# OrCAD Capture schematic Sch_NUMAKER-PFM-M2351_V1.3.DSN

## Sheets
1 Page09_SPI Flash: size A4; title: SPI Flash(W77FXX); rev: V1.3; note: NuMaker-PFM-M2351
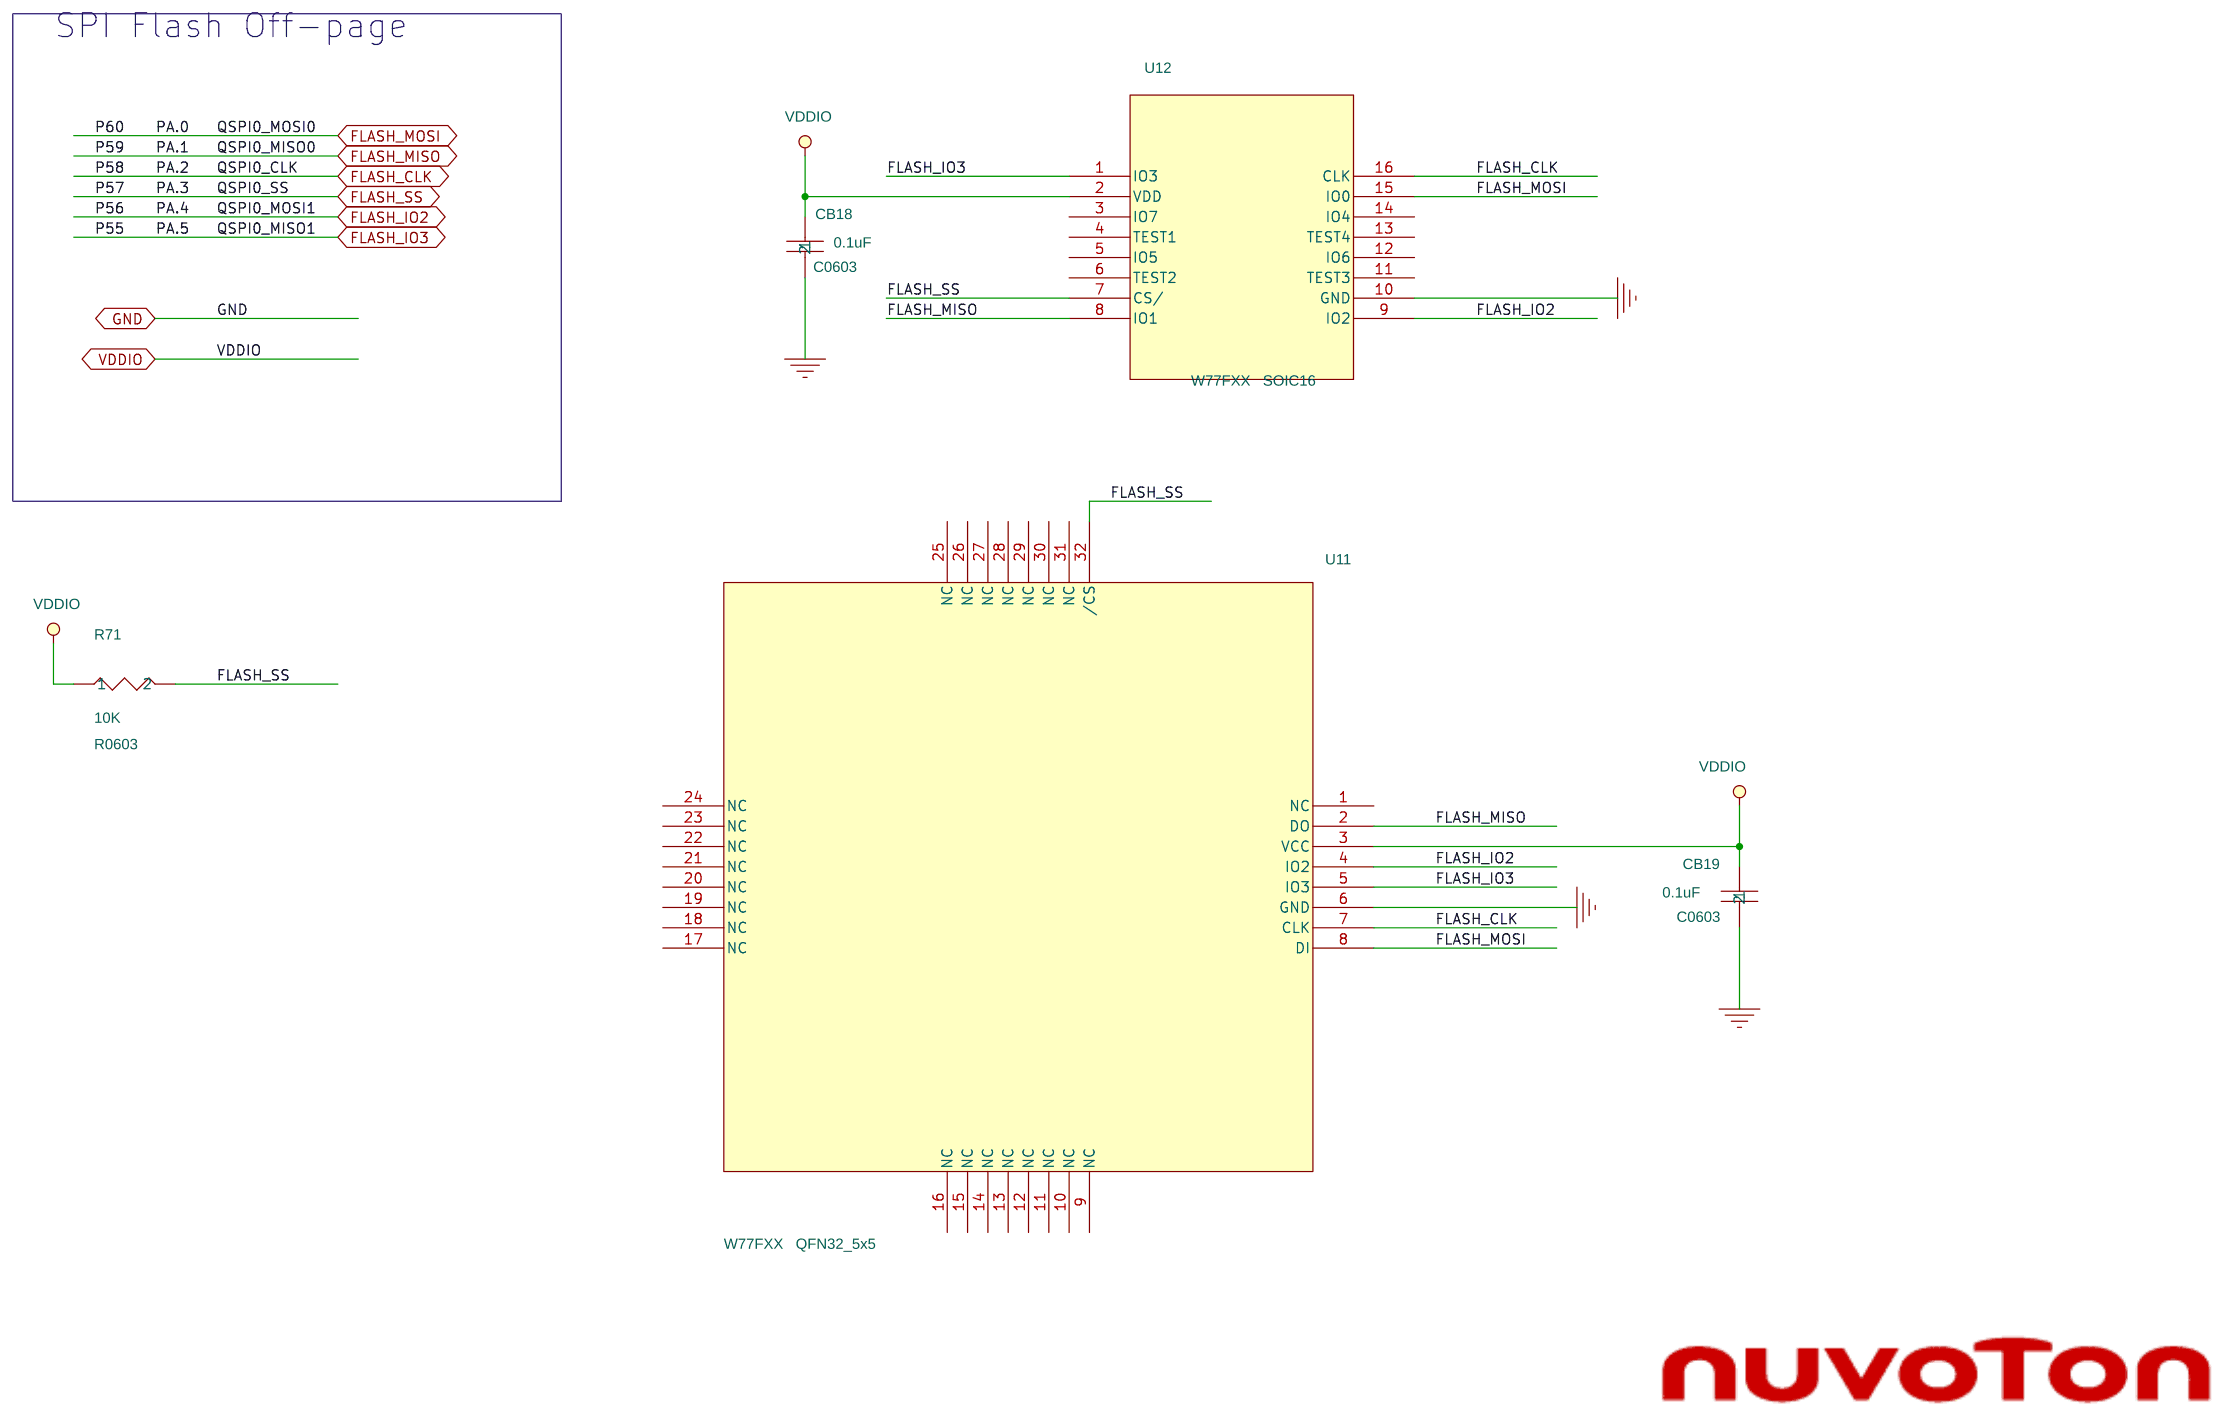
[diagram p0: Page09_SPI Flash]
2 Page08_WIFI Module: size A4; title: WIFI Module(ESP-03)
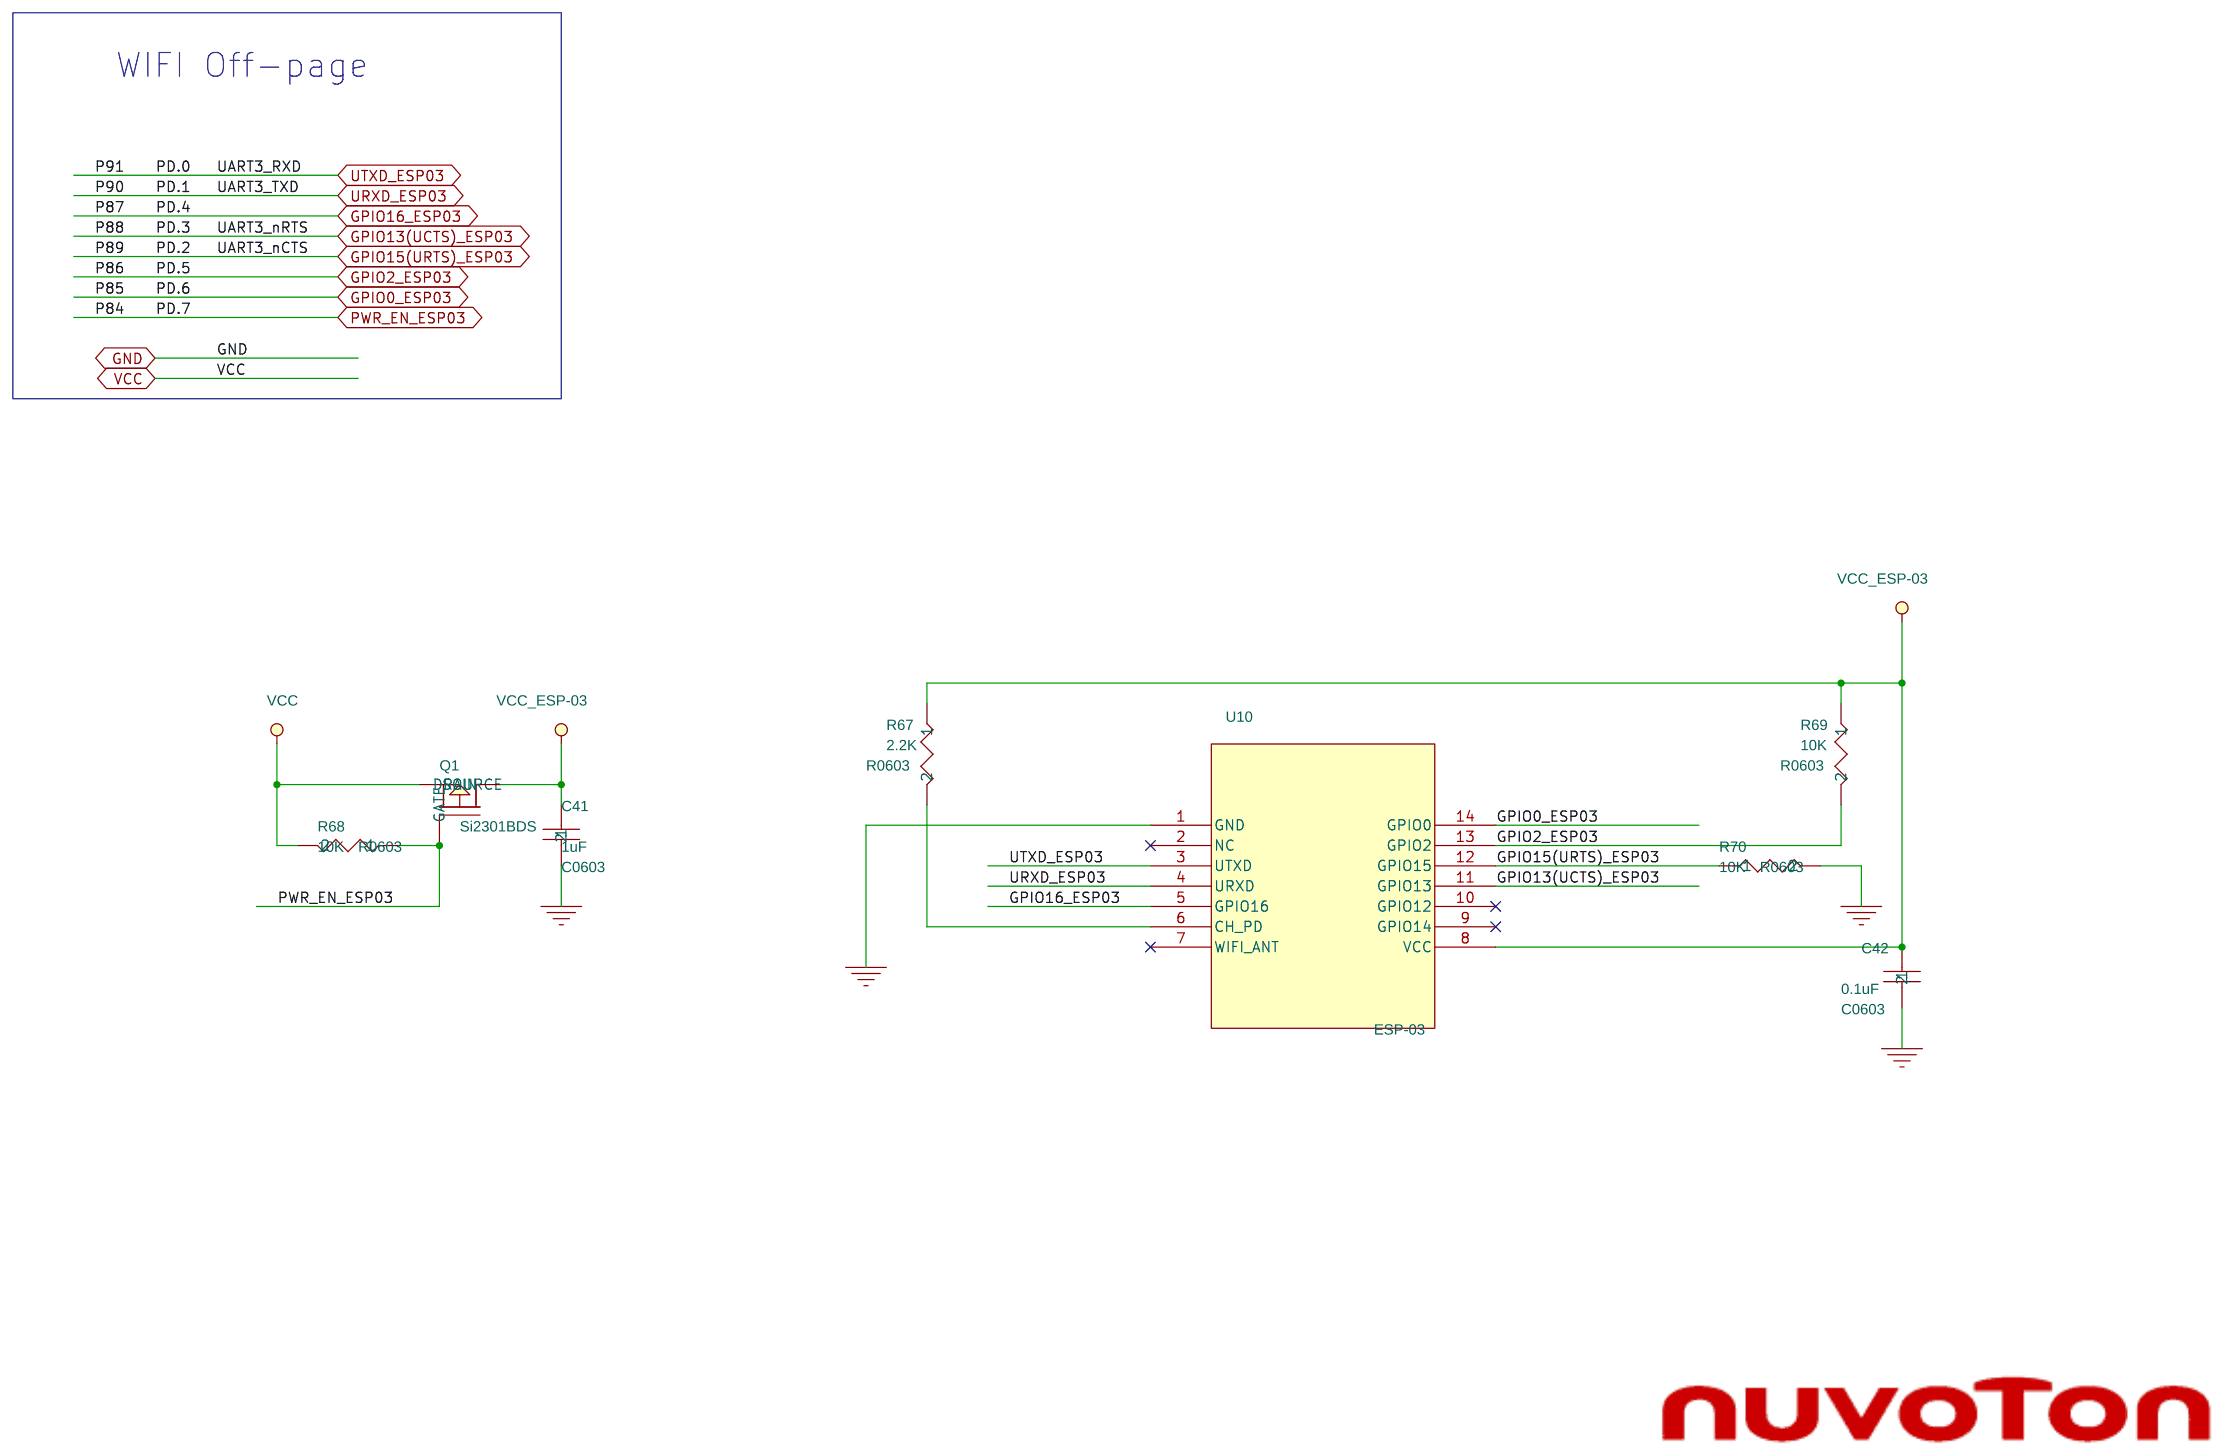
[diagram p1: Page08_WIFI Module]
3 Page00_Nu-Link-Me V3.0: size Custom; title: Nu-Link-Me(V3.0)
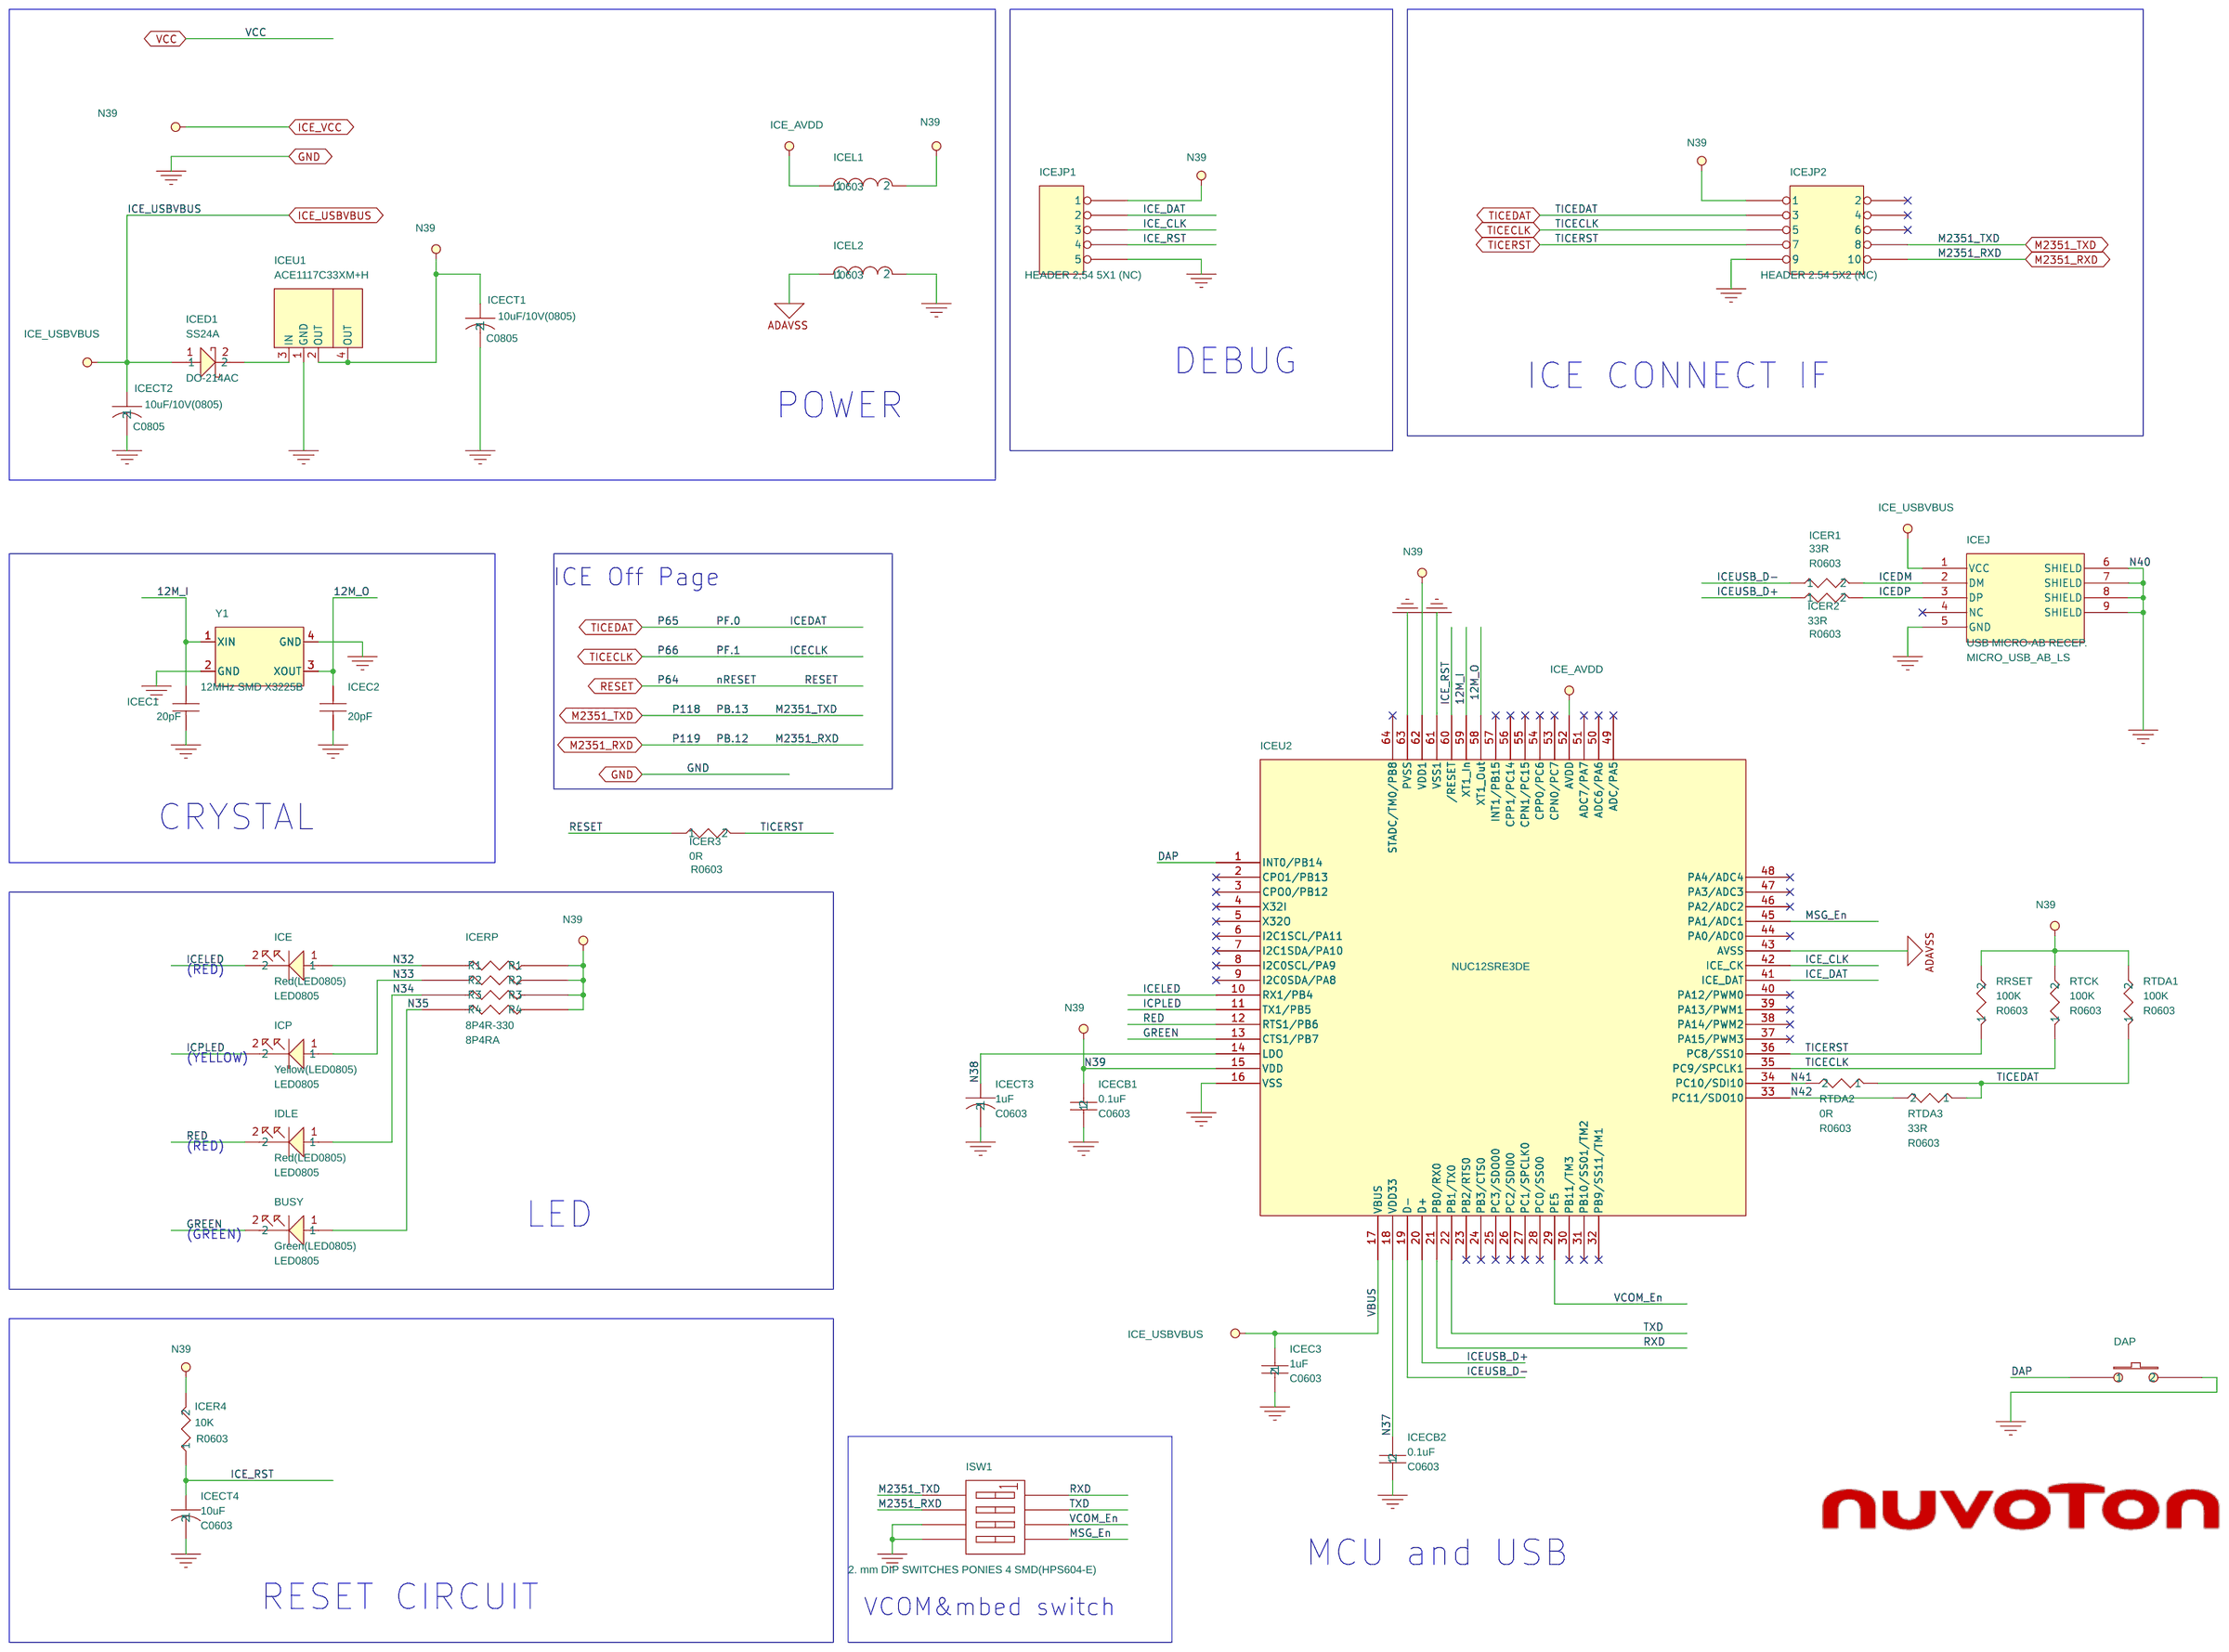
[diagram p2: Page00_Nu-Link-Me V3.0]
4 Page01_M2351 MCU: size Custom; title: M2351KIAAE(LQFP128) MCU
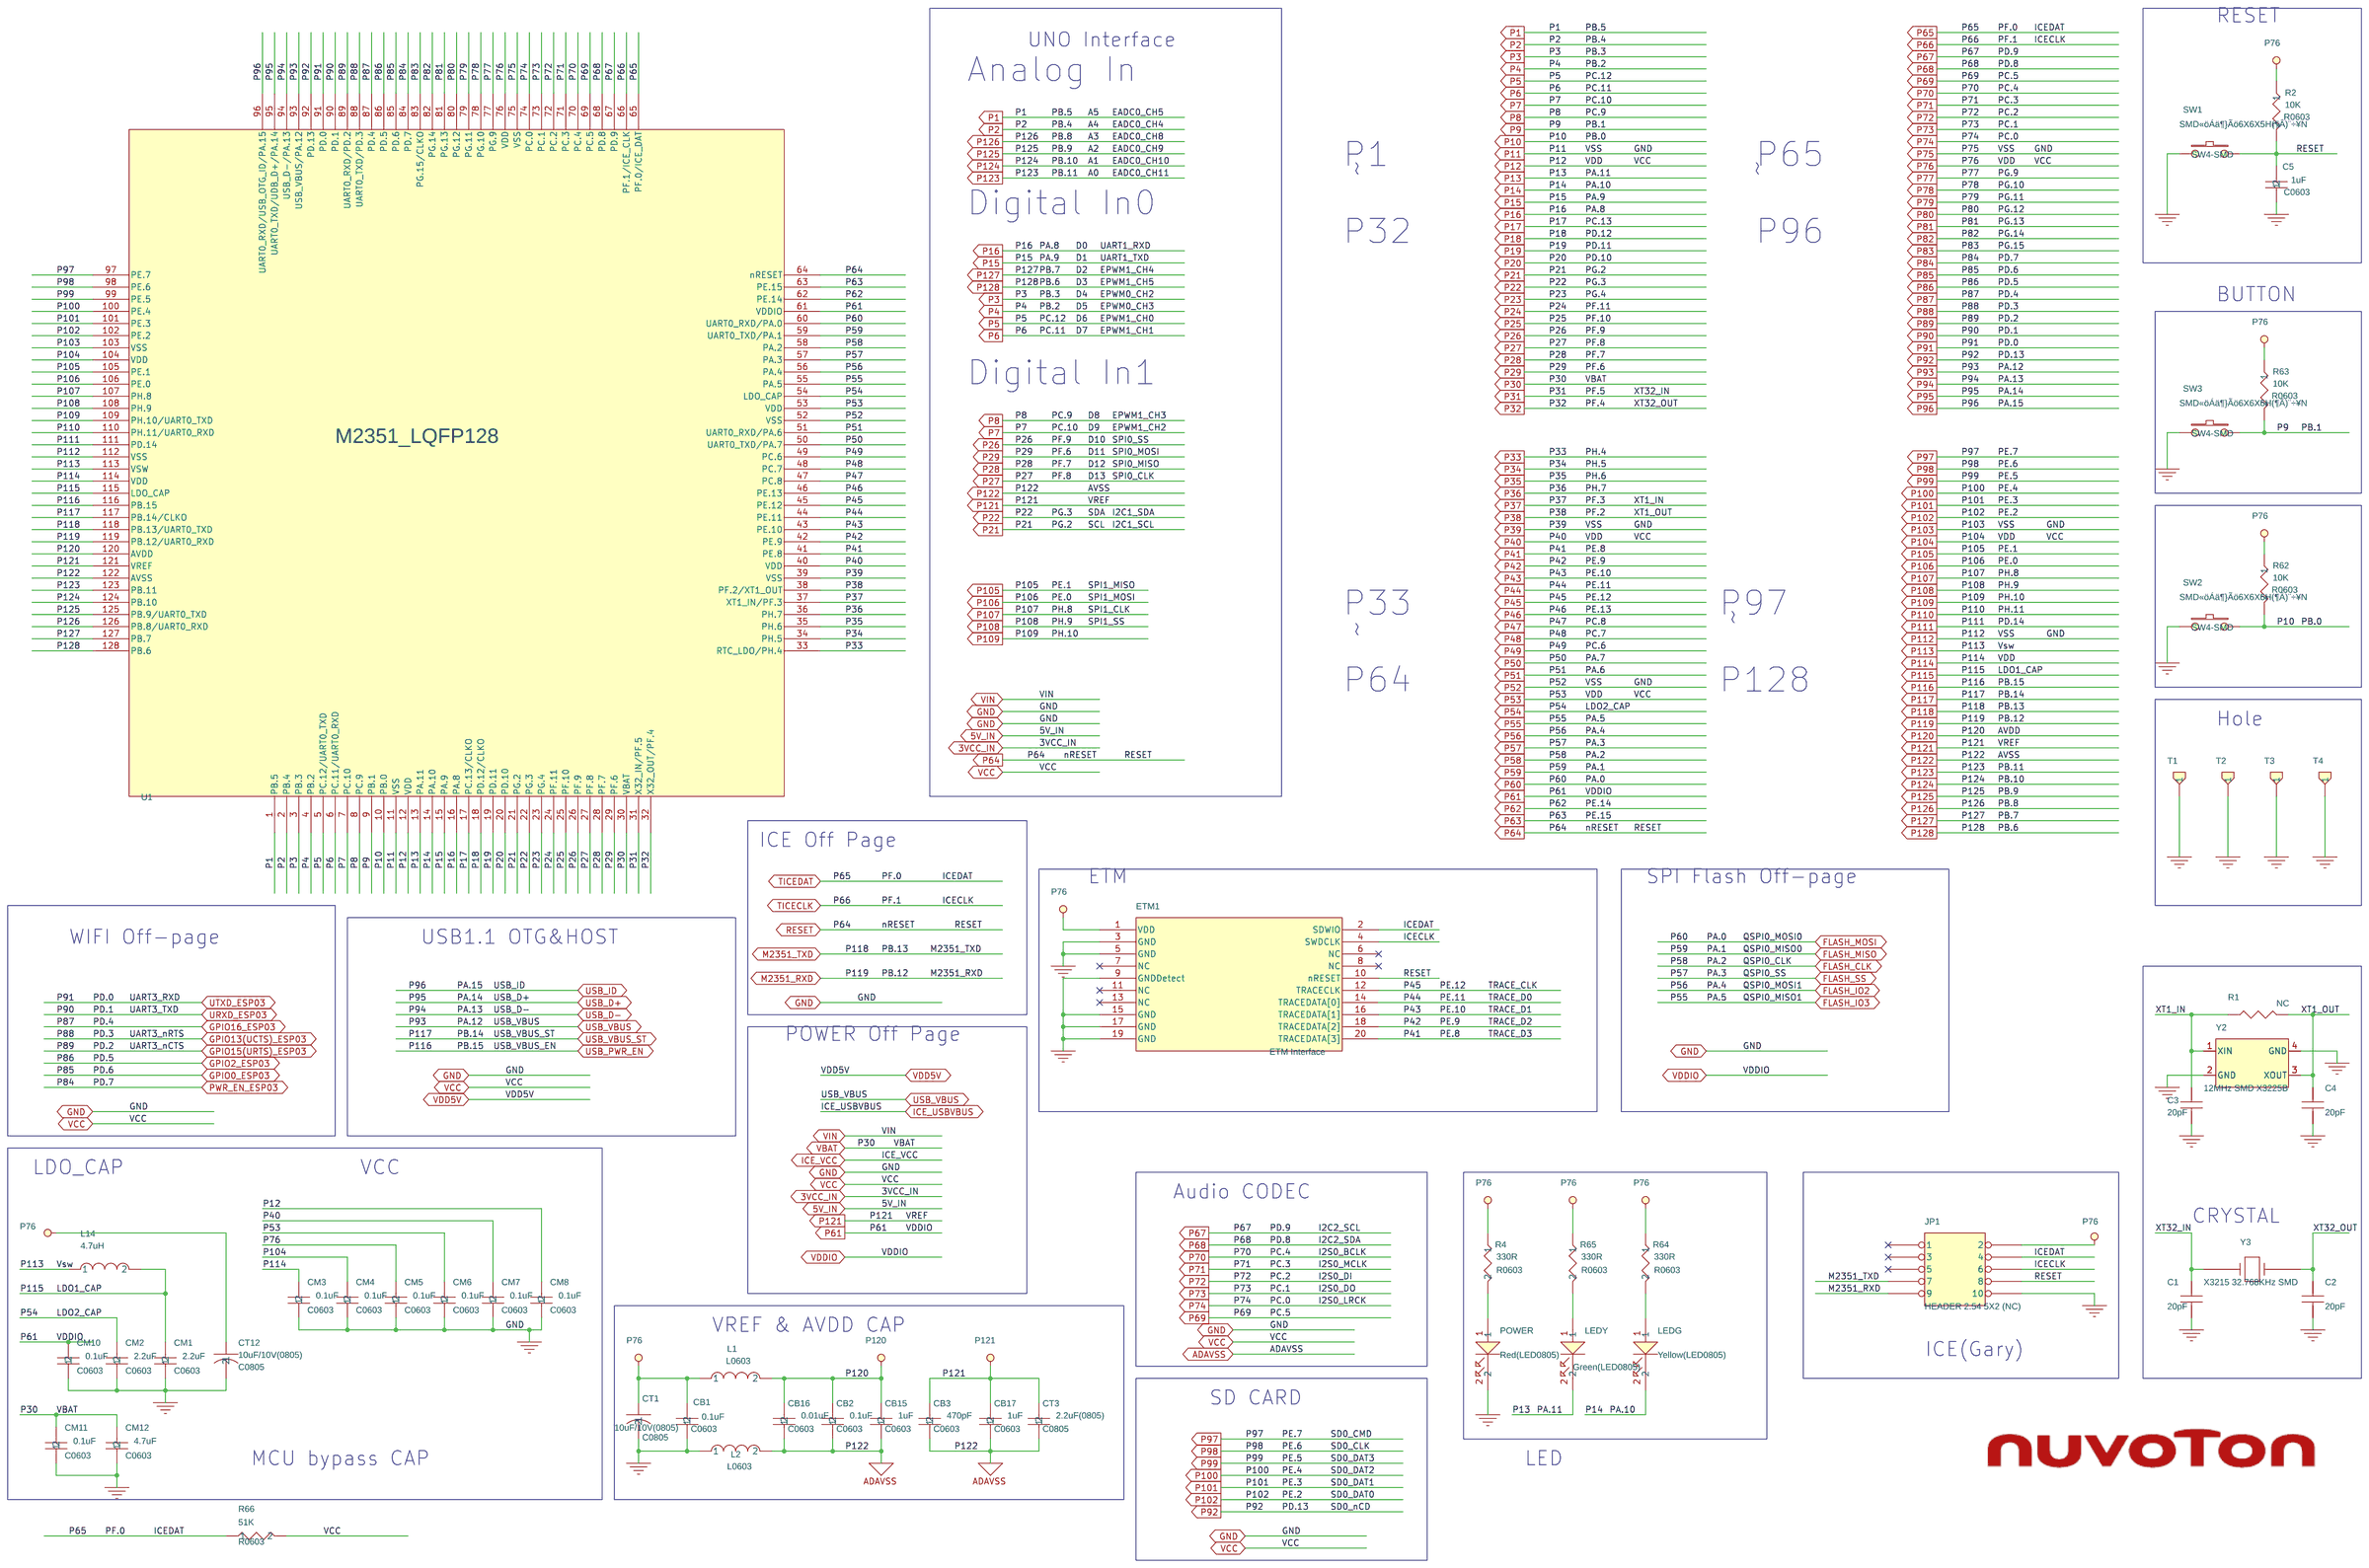
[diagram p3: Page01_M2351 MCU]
5 Page02_USB OTG Host Device: size A4; title: USB OTG
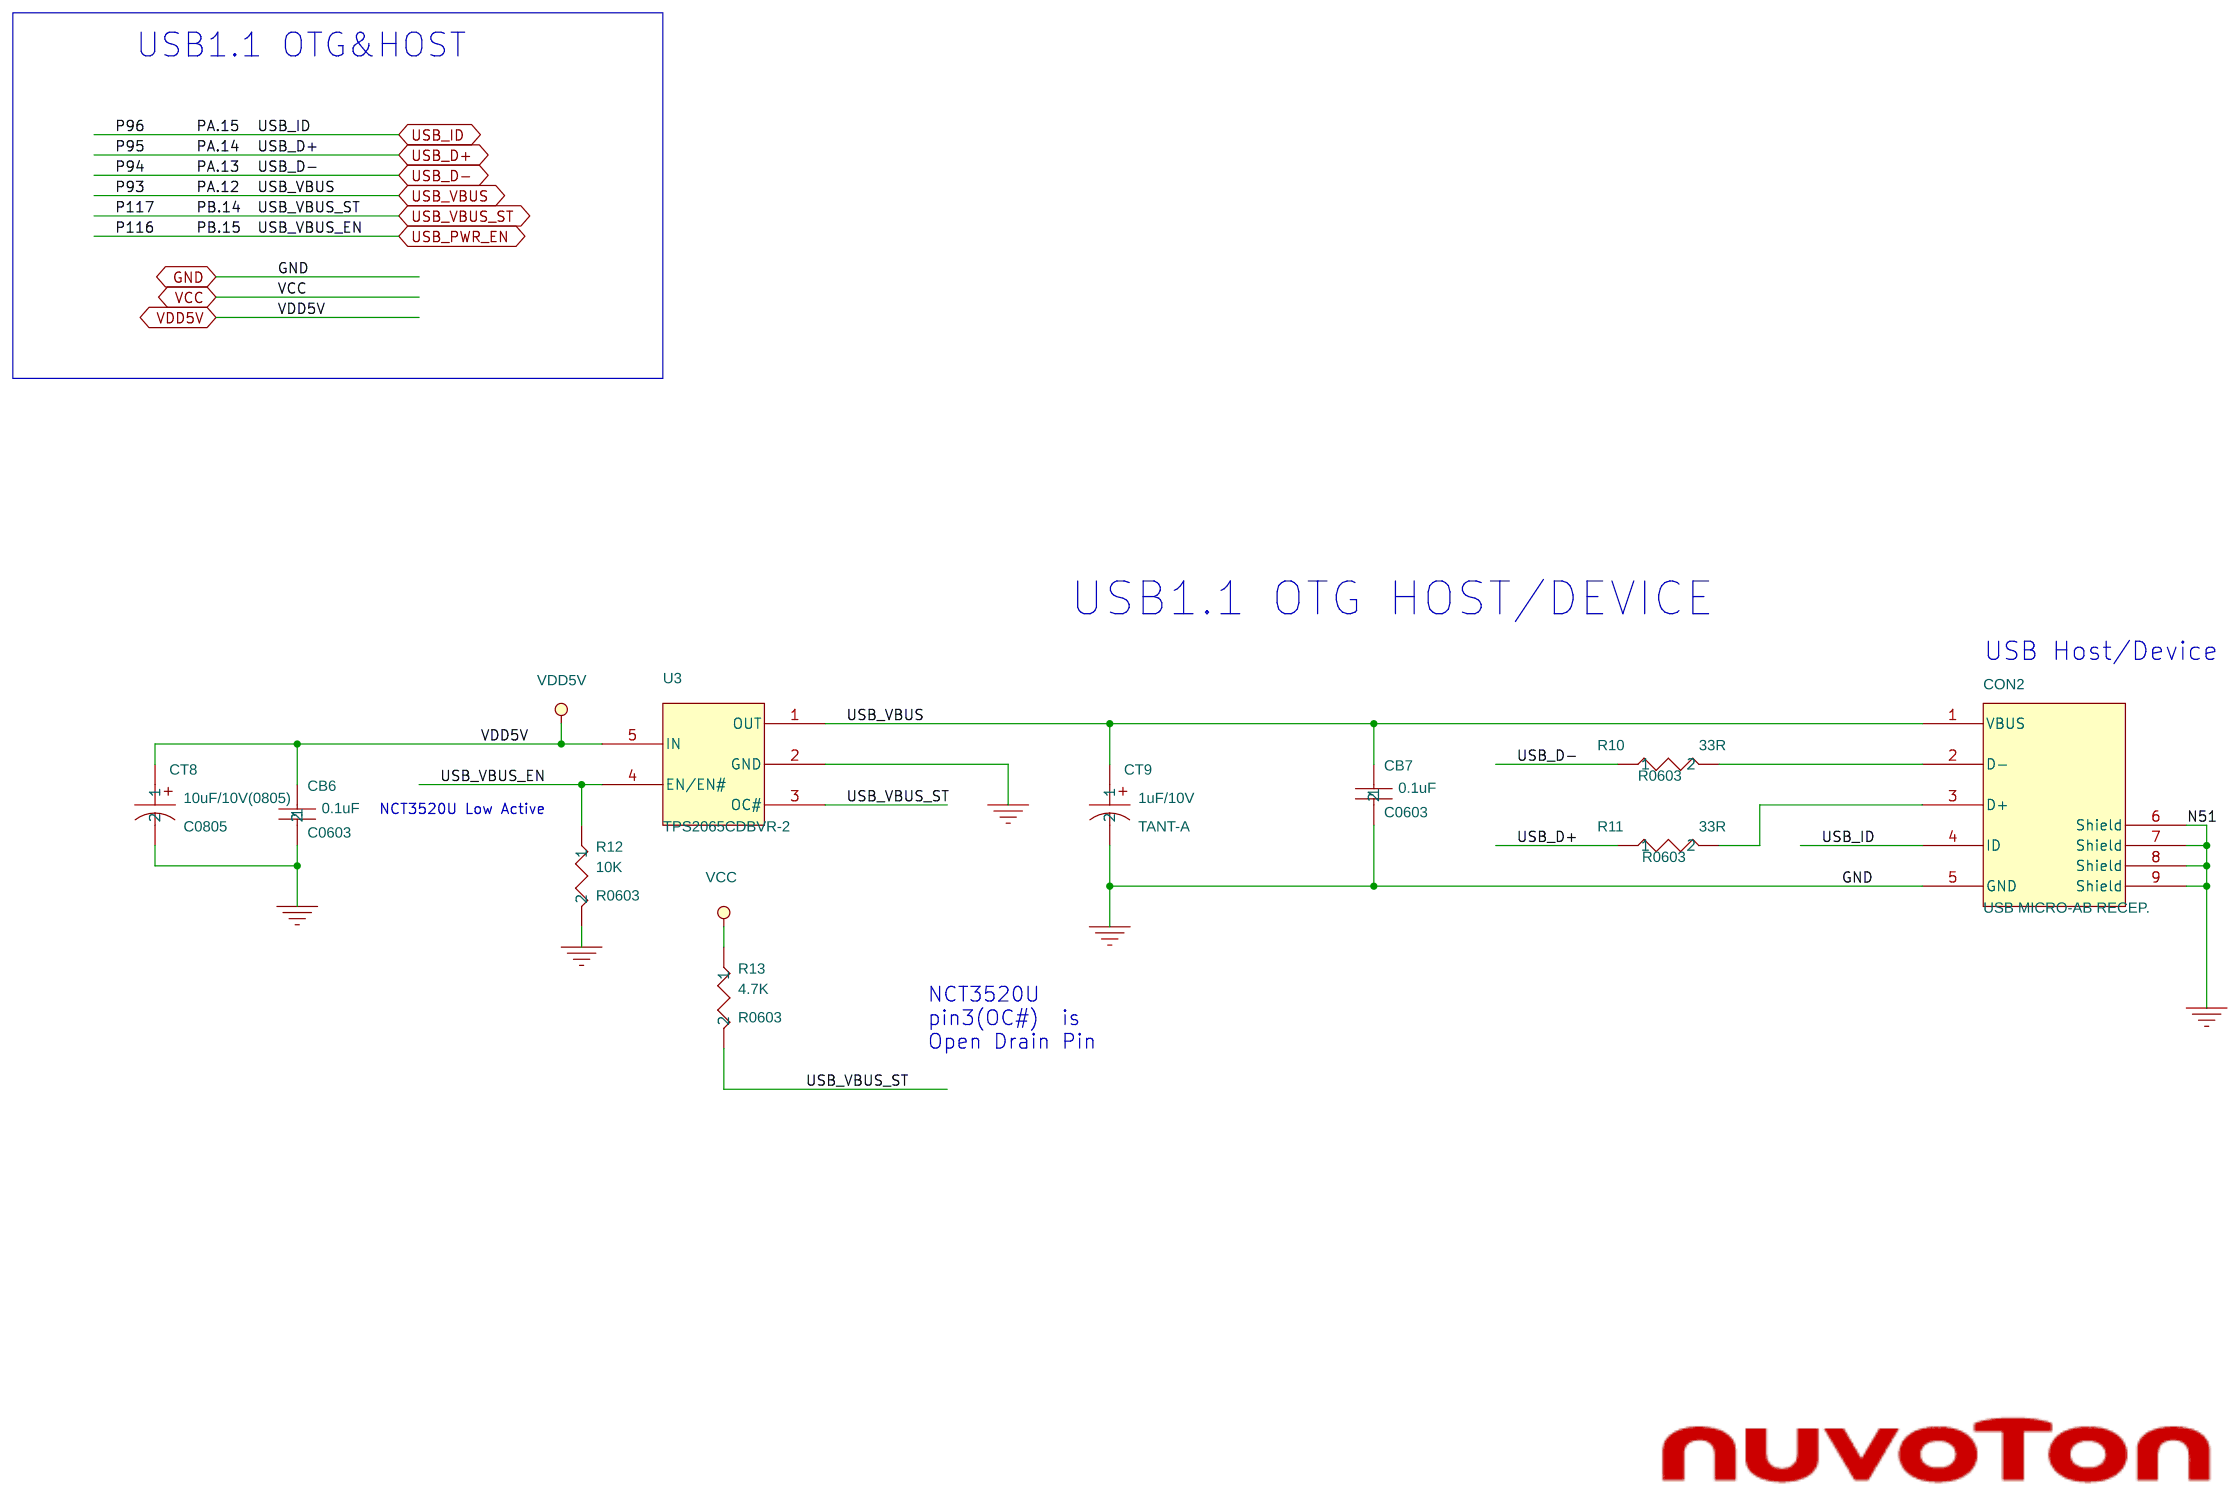
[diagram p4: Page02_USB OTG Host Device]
6 Page03_Power: size A; title: POWER
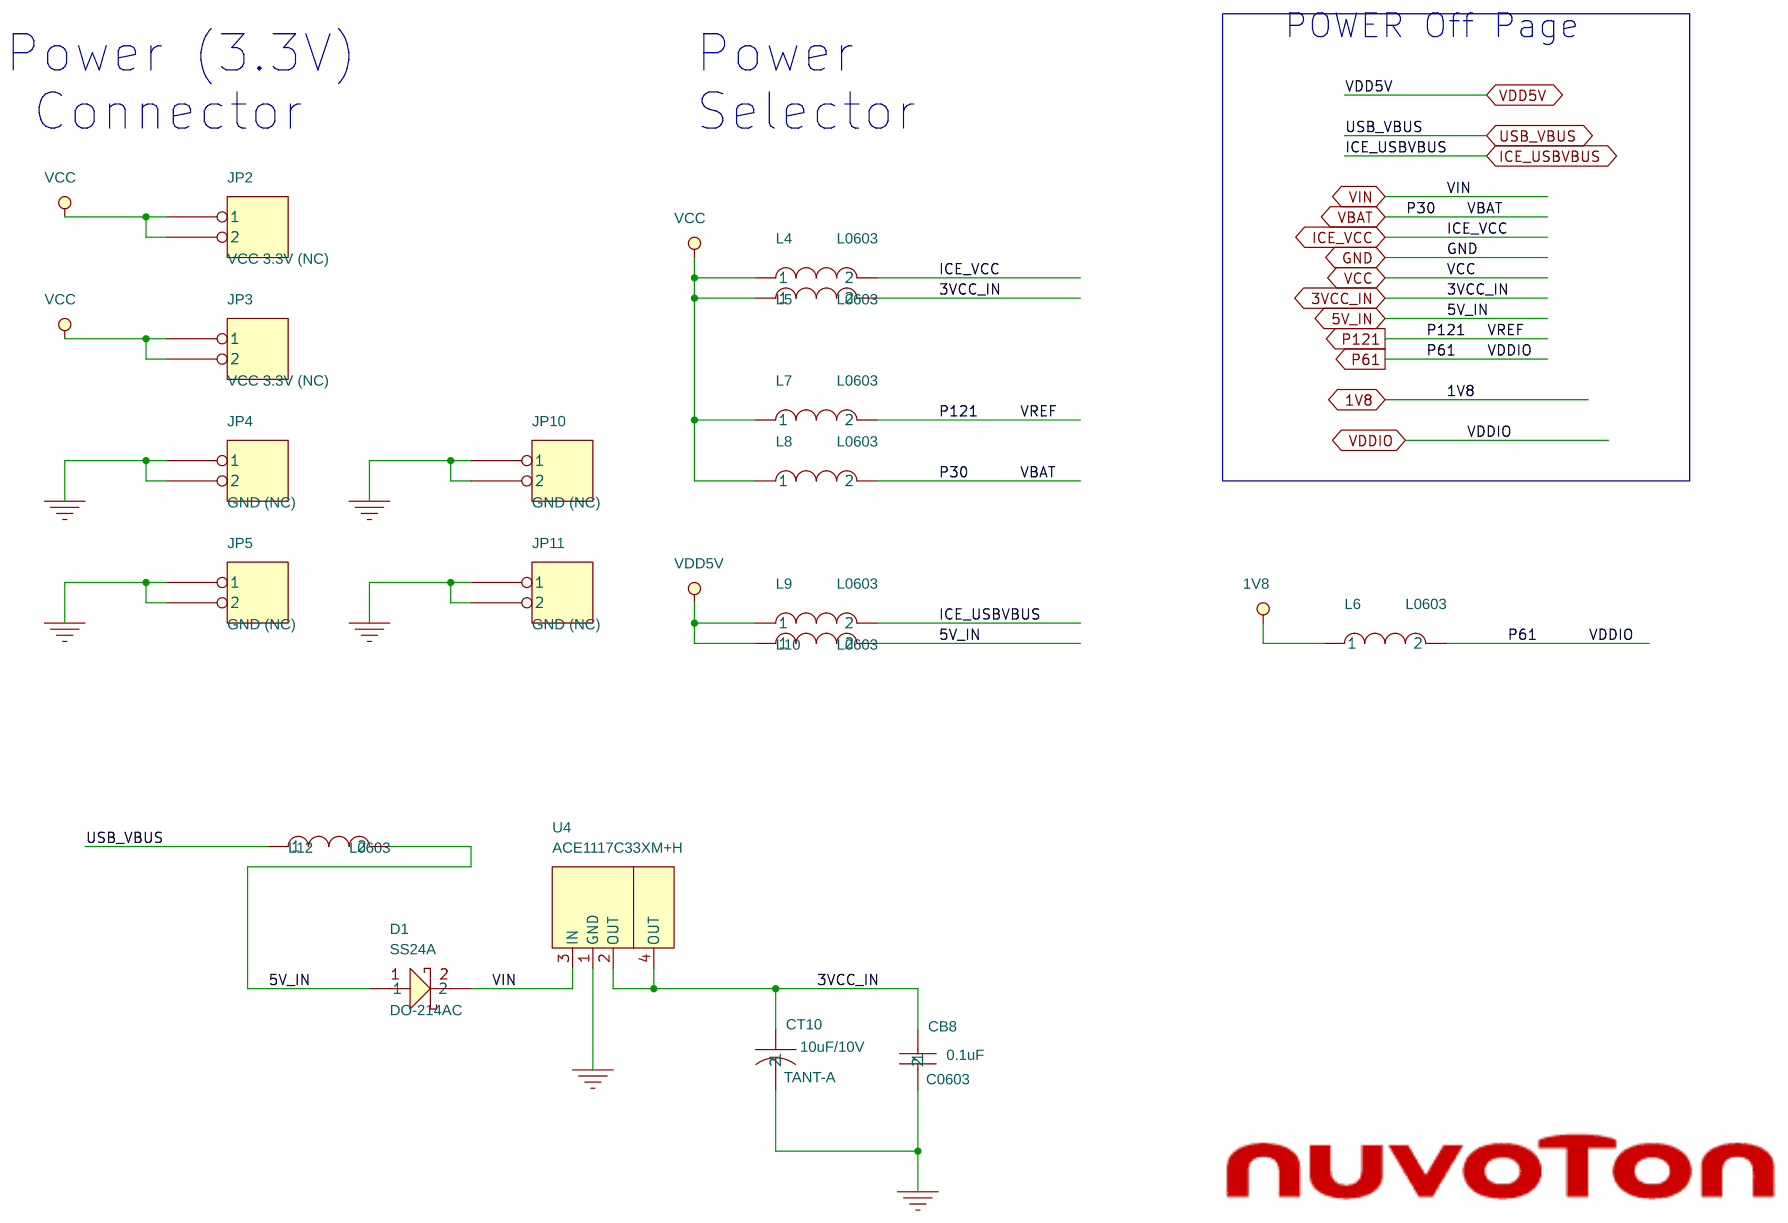
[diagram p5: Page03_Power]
7 Page04_MCU Connector: size A4; title: MCU Connector
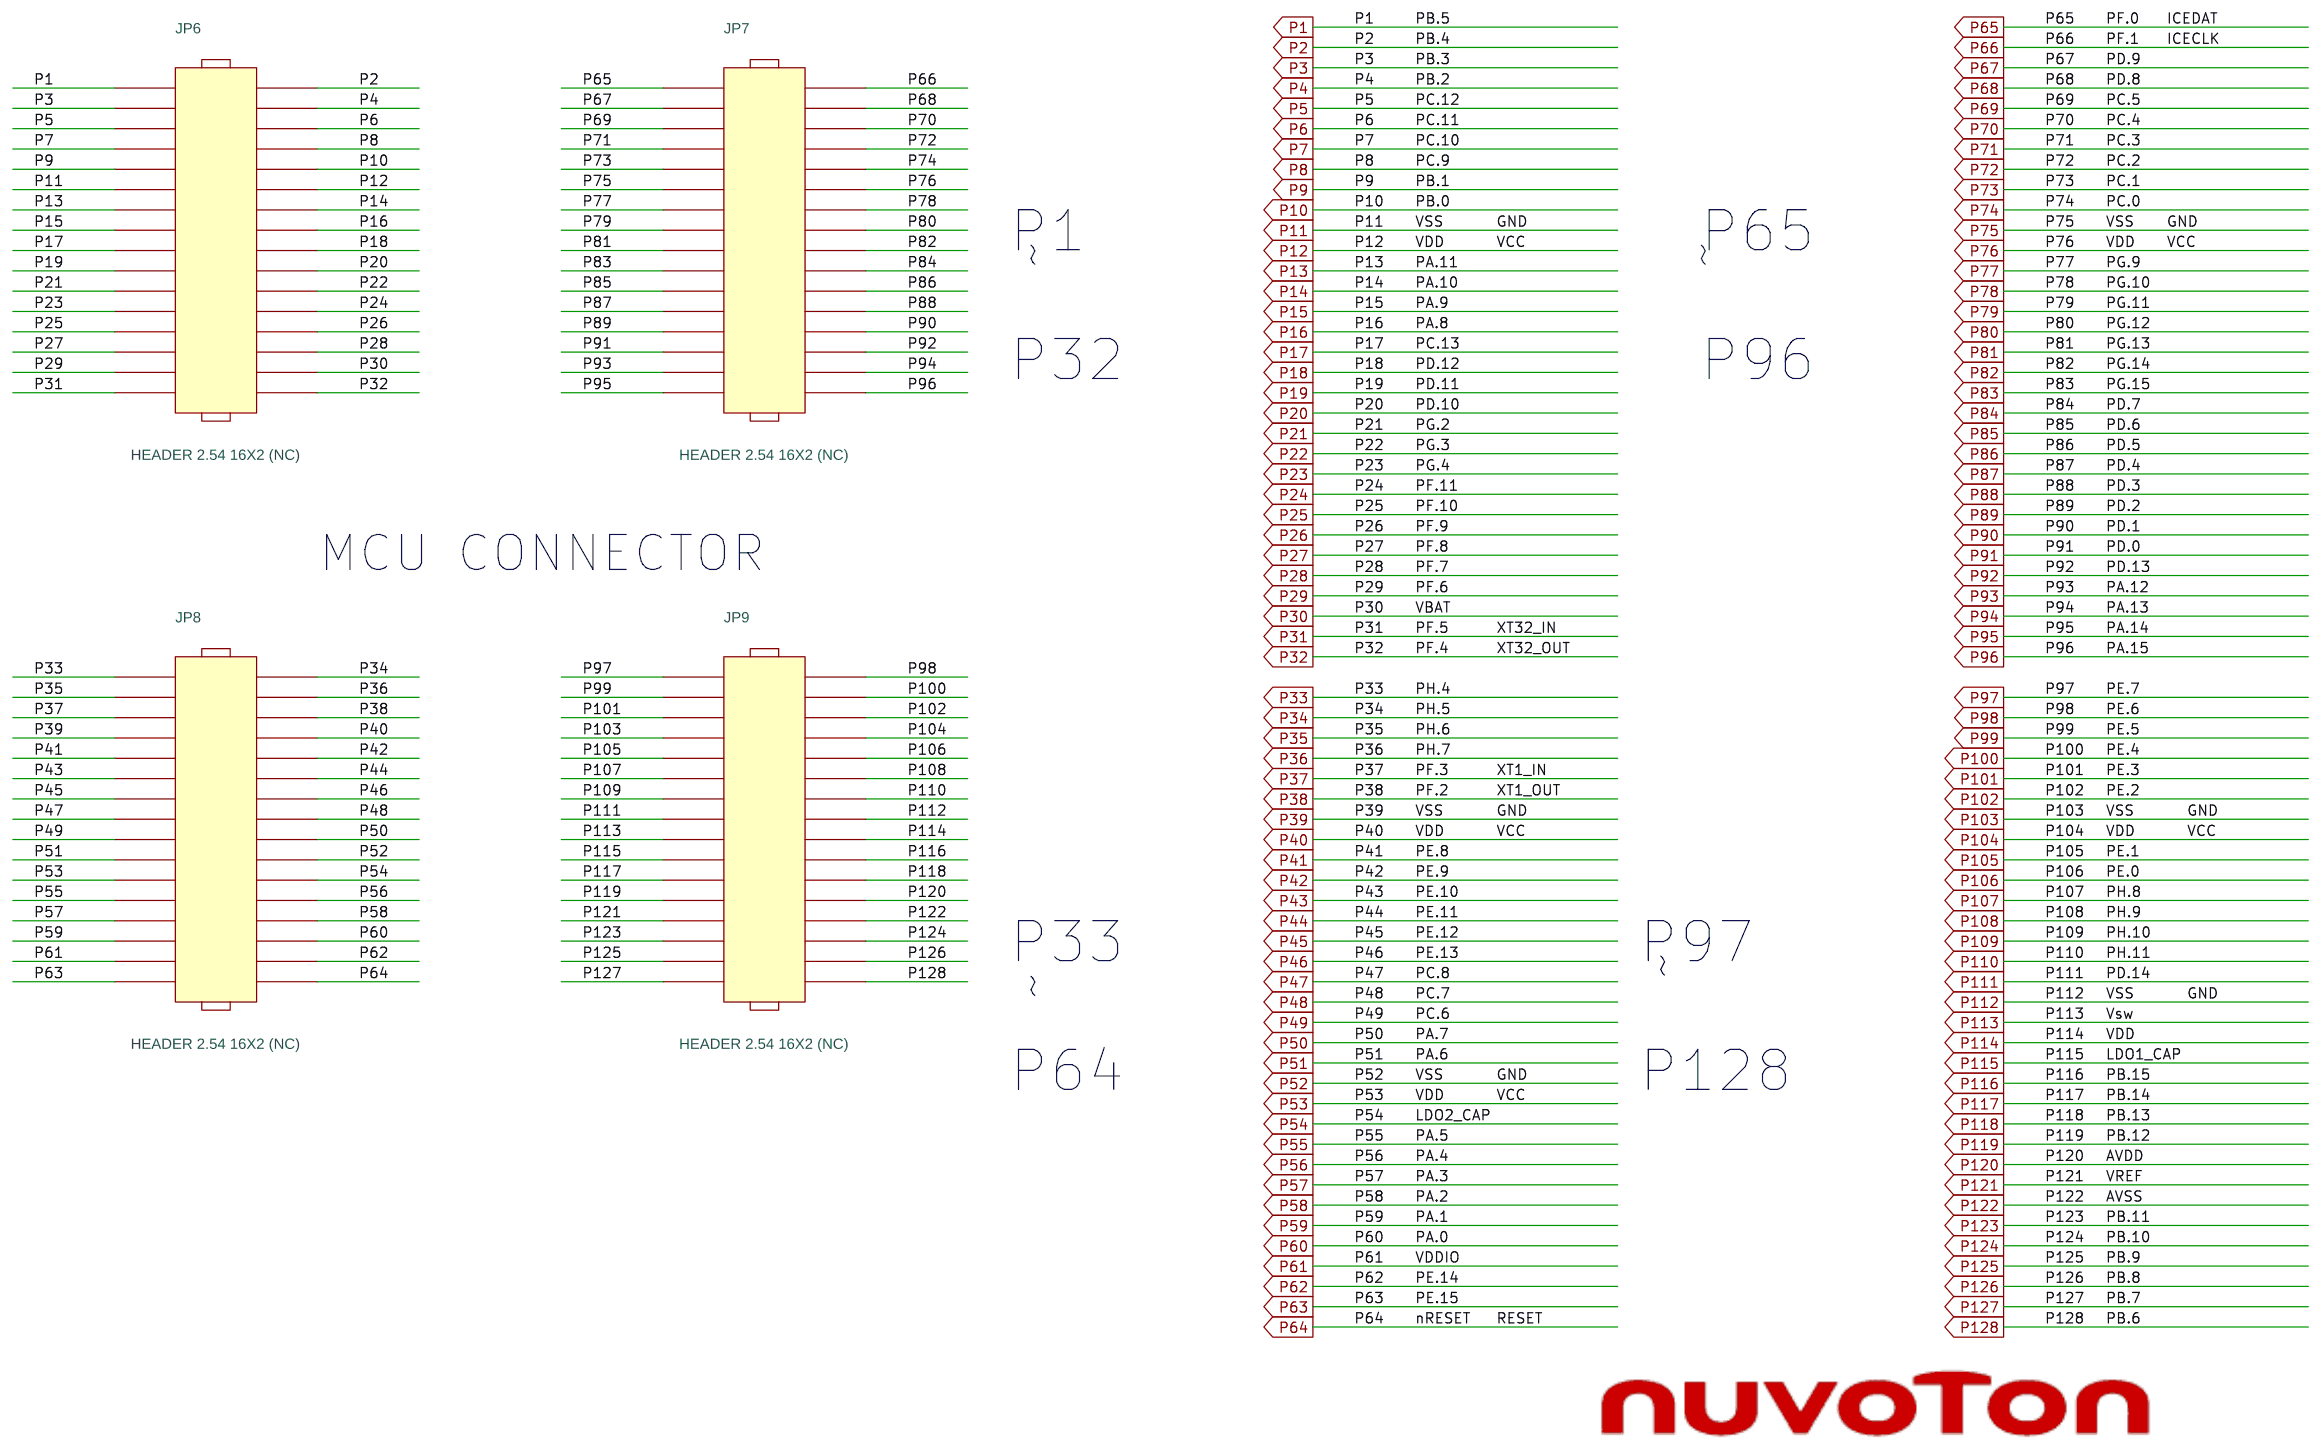
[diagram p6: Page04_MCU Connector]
8 Page05 UNO Interface Connector: size A; title: UNO Interface
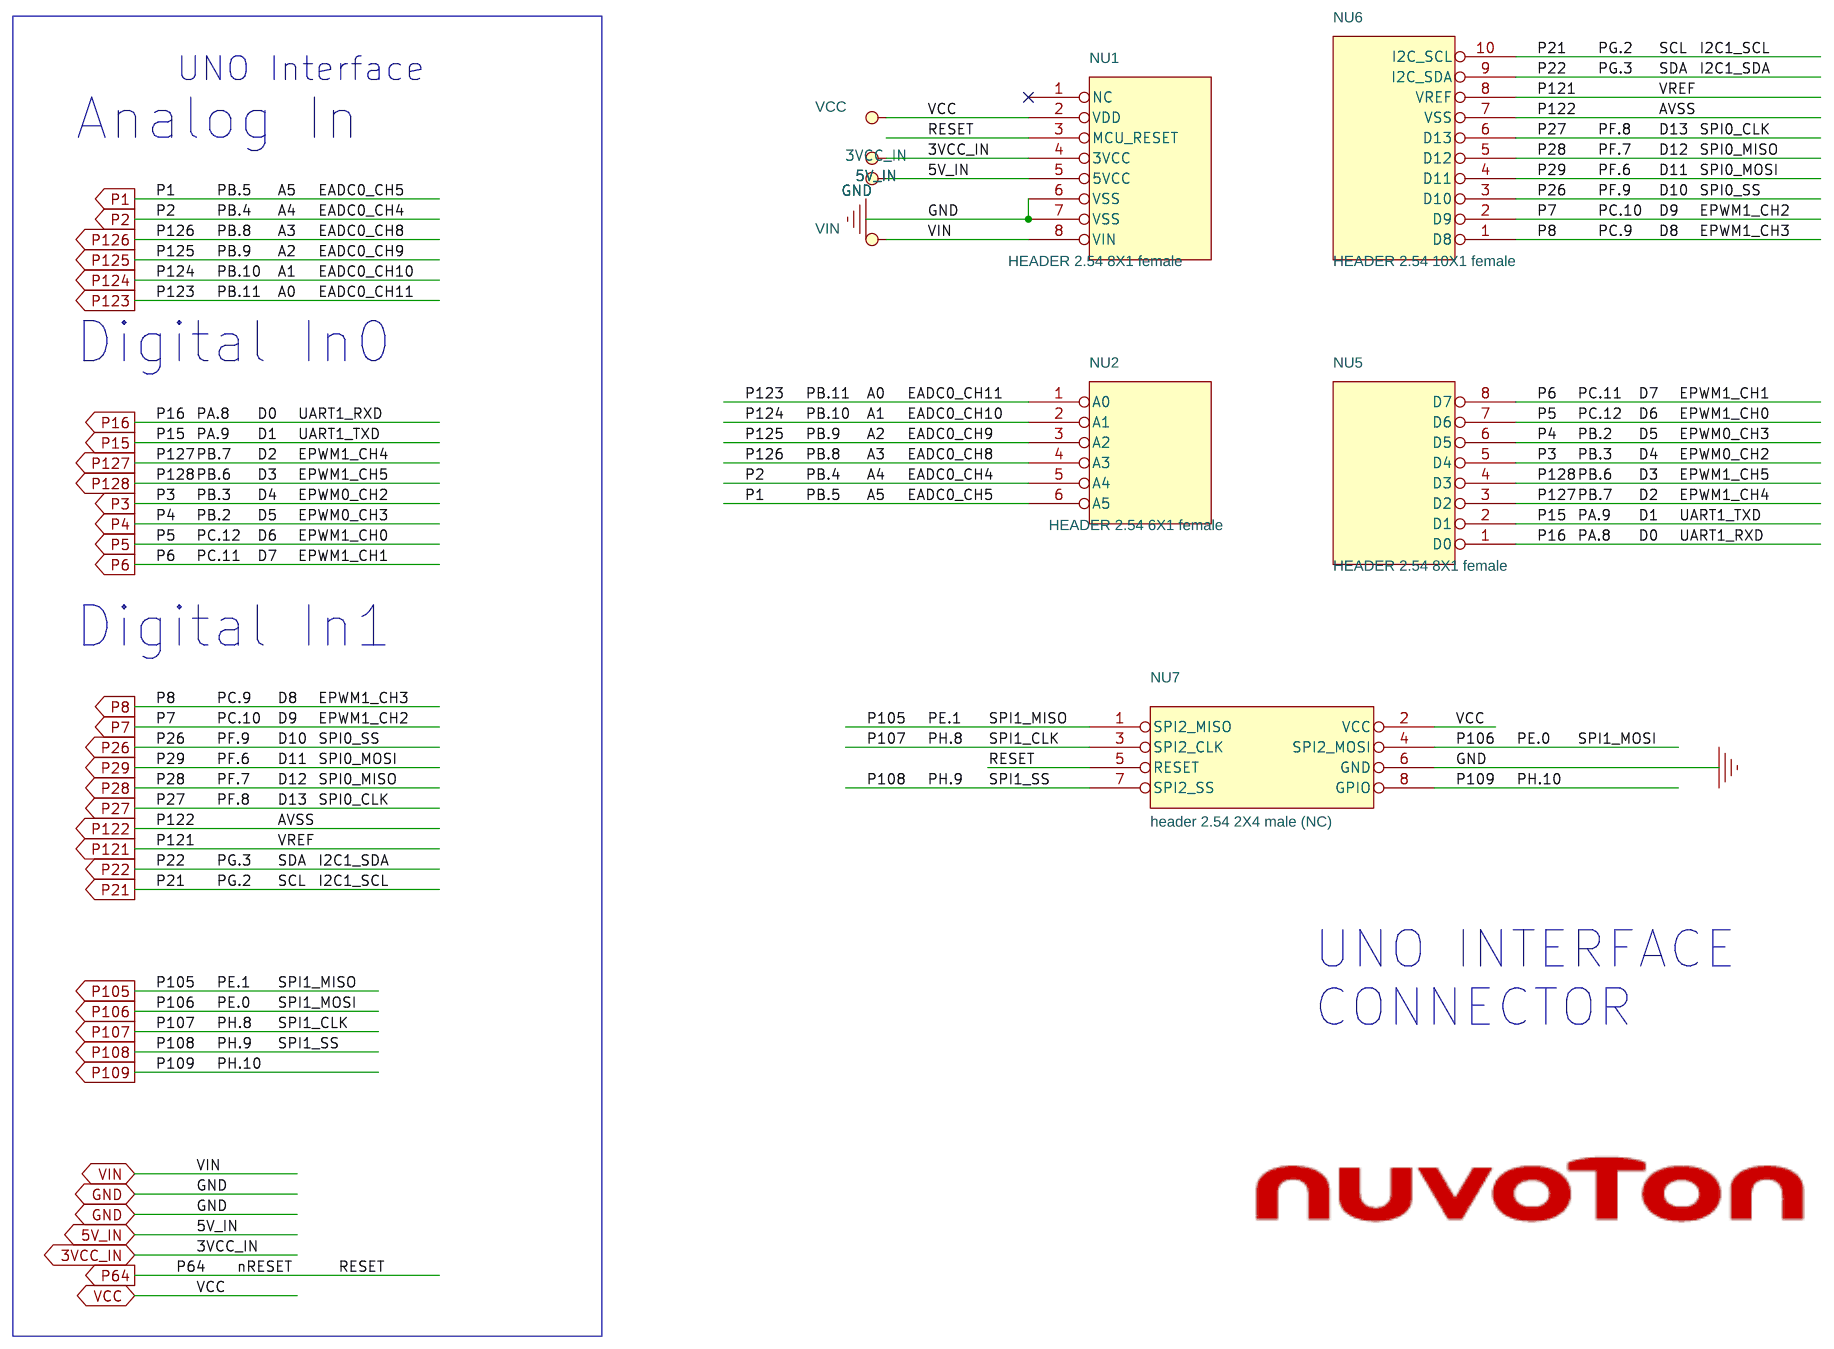
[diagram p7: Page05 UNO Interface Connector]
9 Page06_Audio Codec: size A3; title: Audio Codec
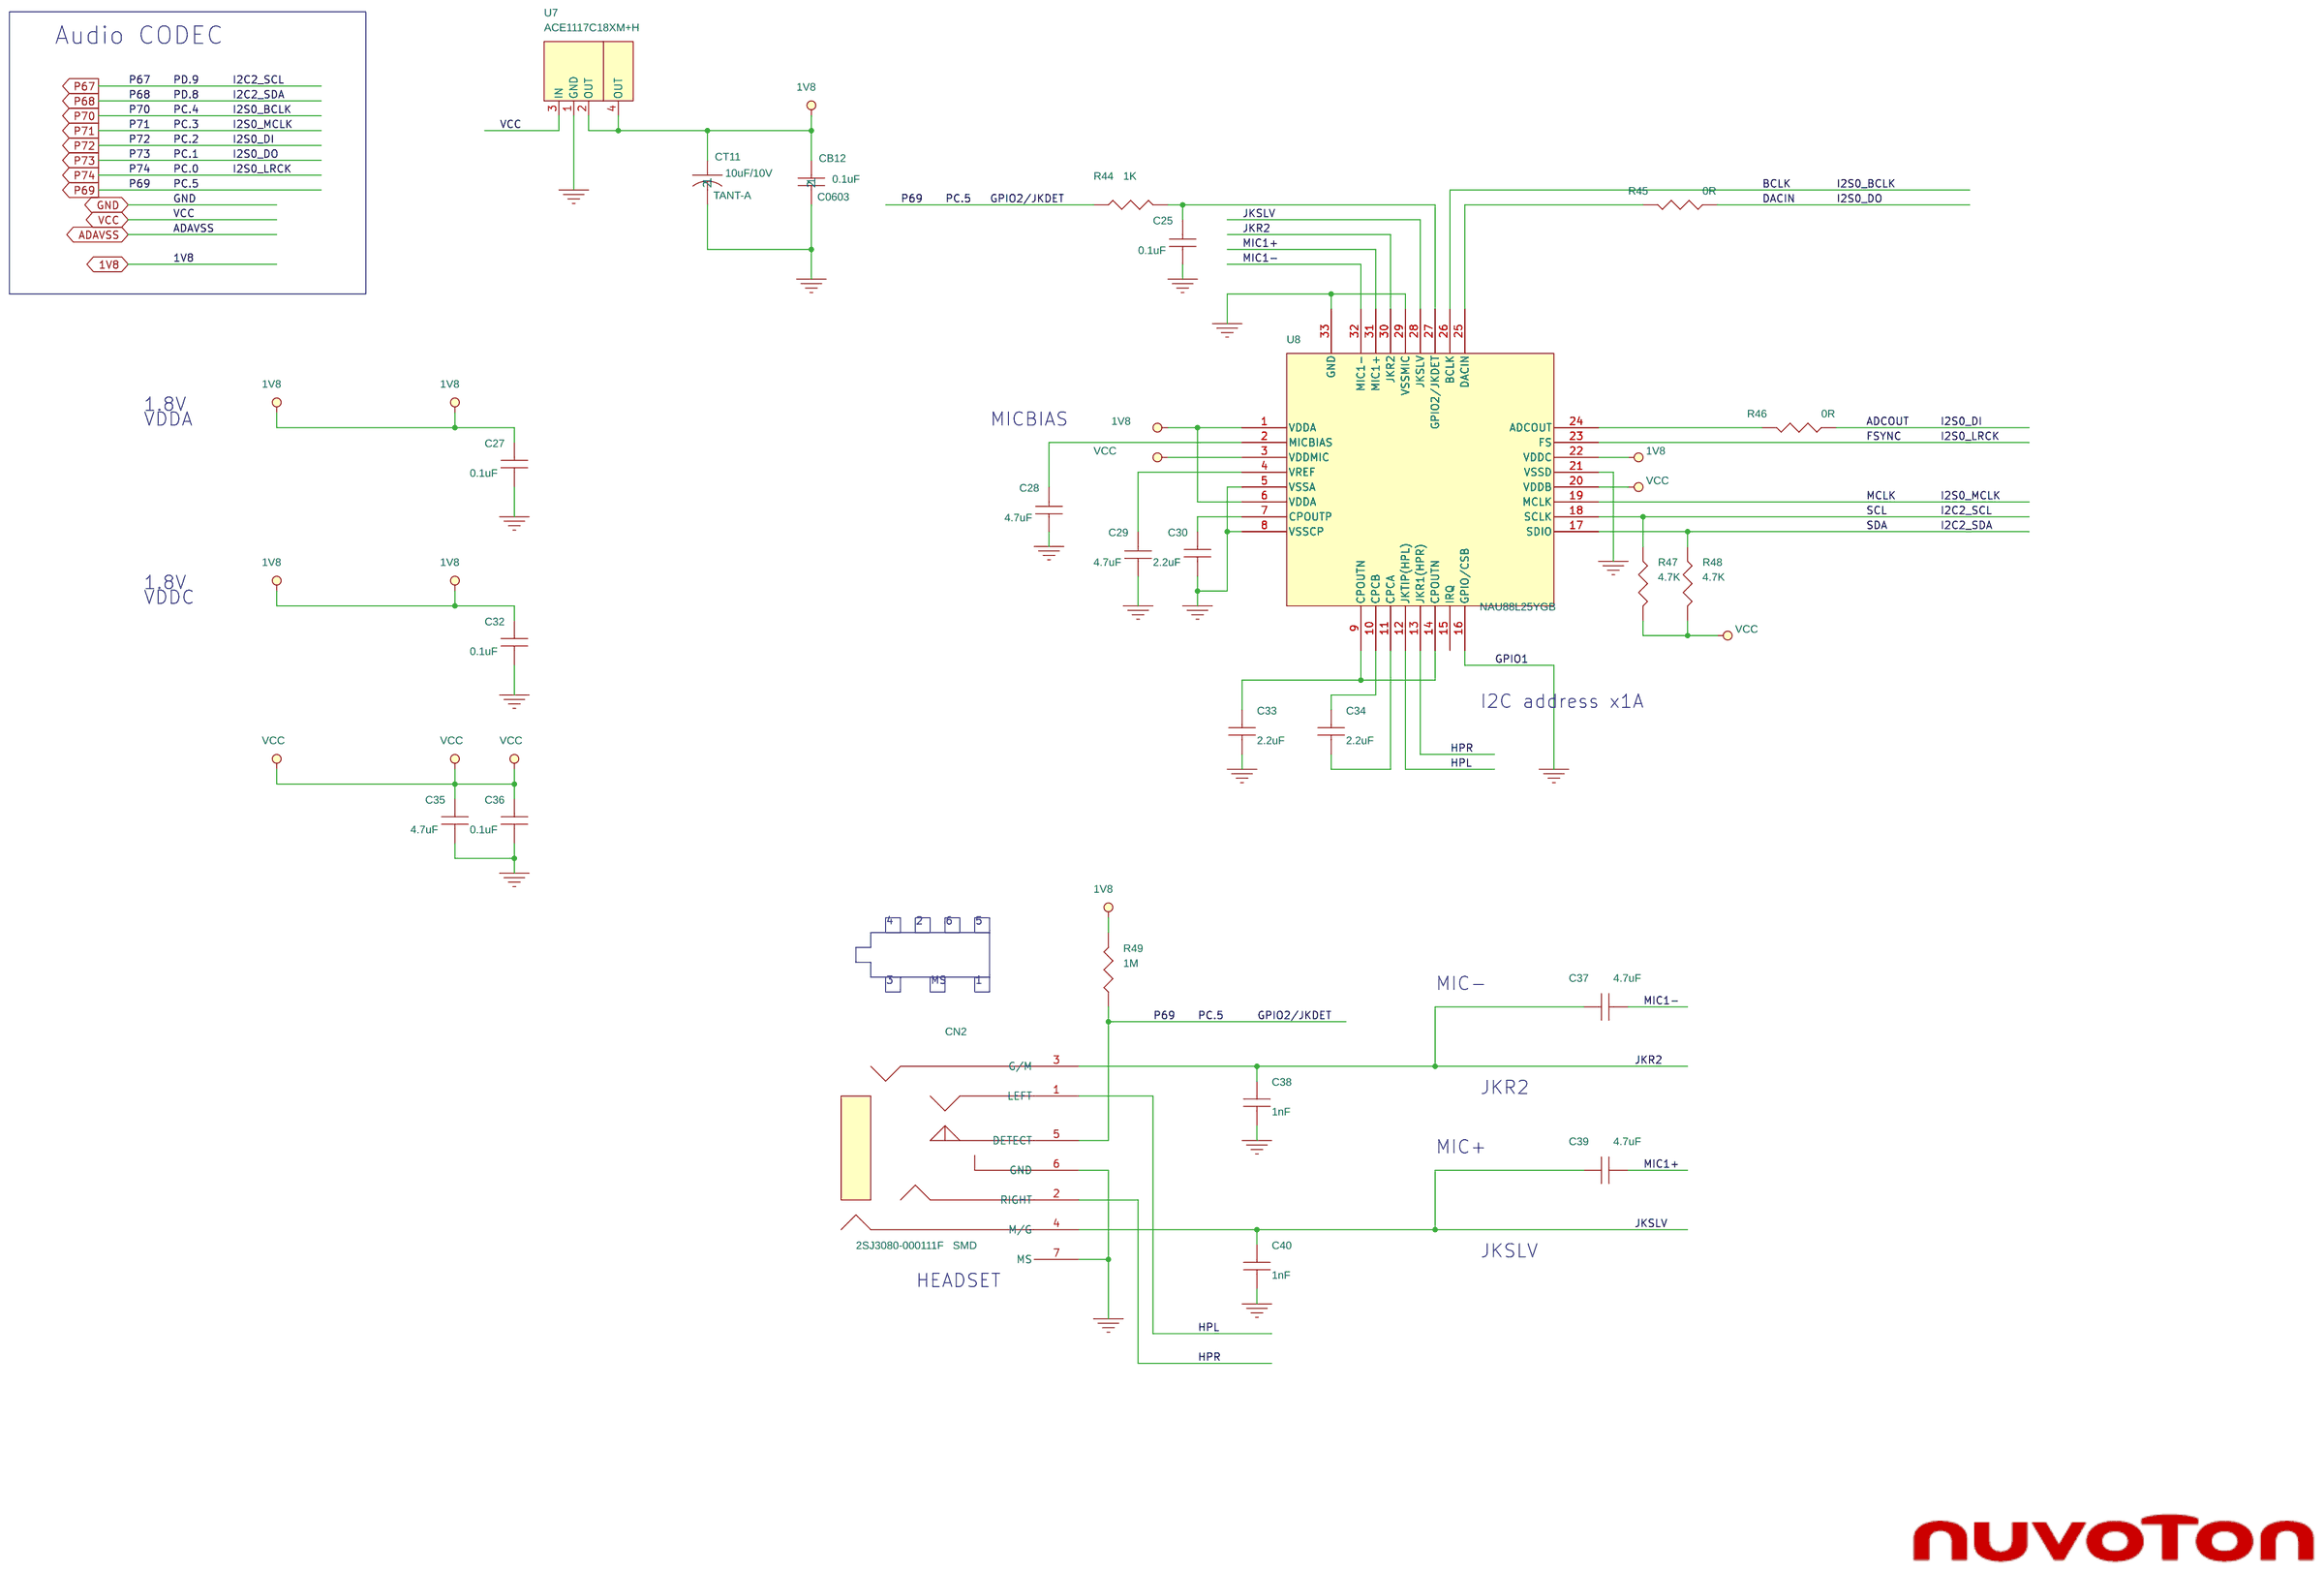
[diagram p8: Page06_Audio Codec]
10 Page07_SD Card: size A4; title: SD Card
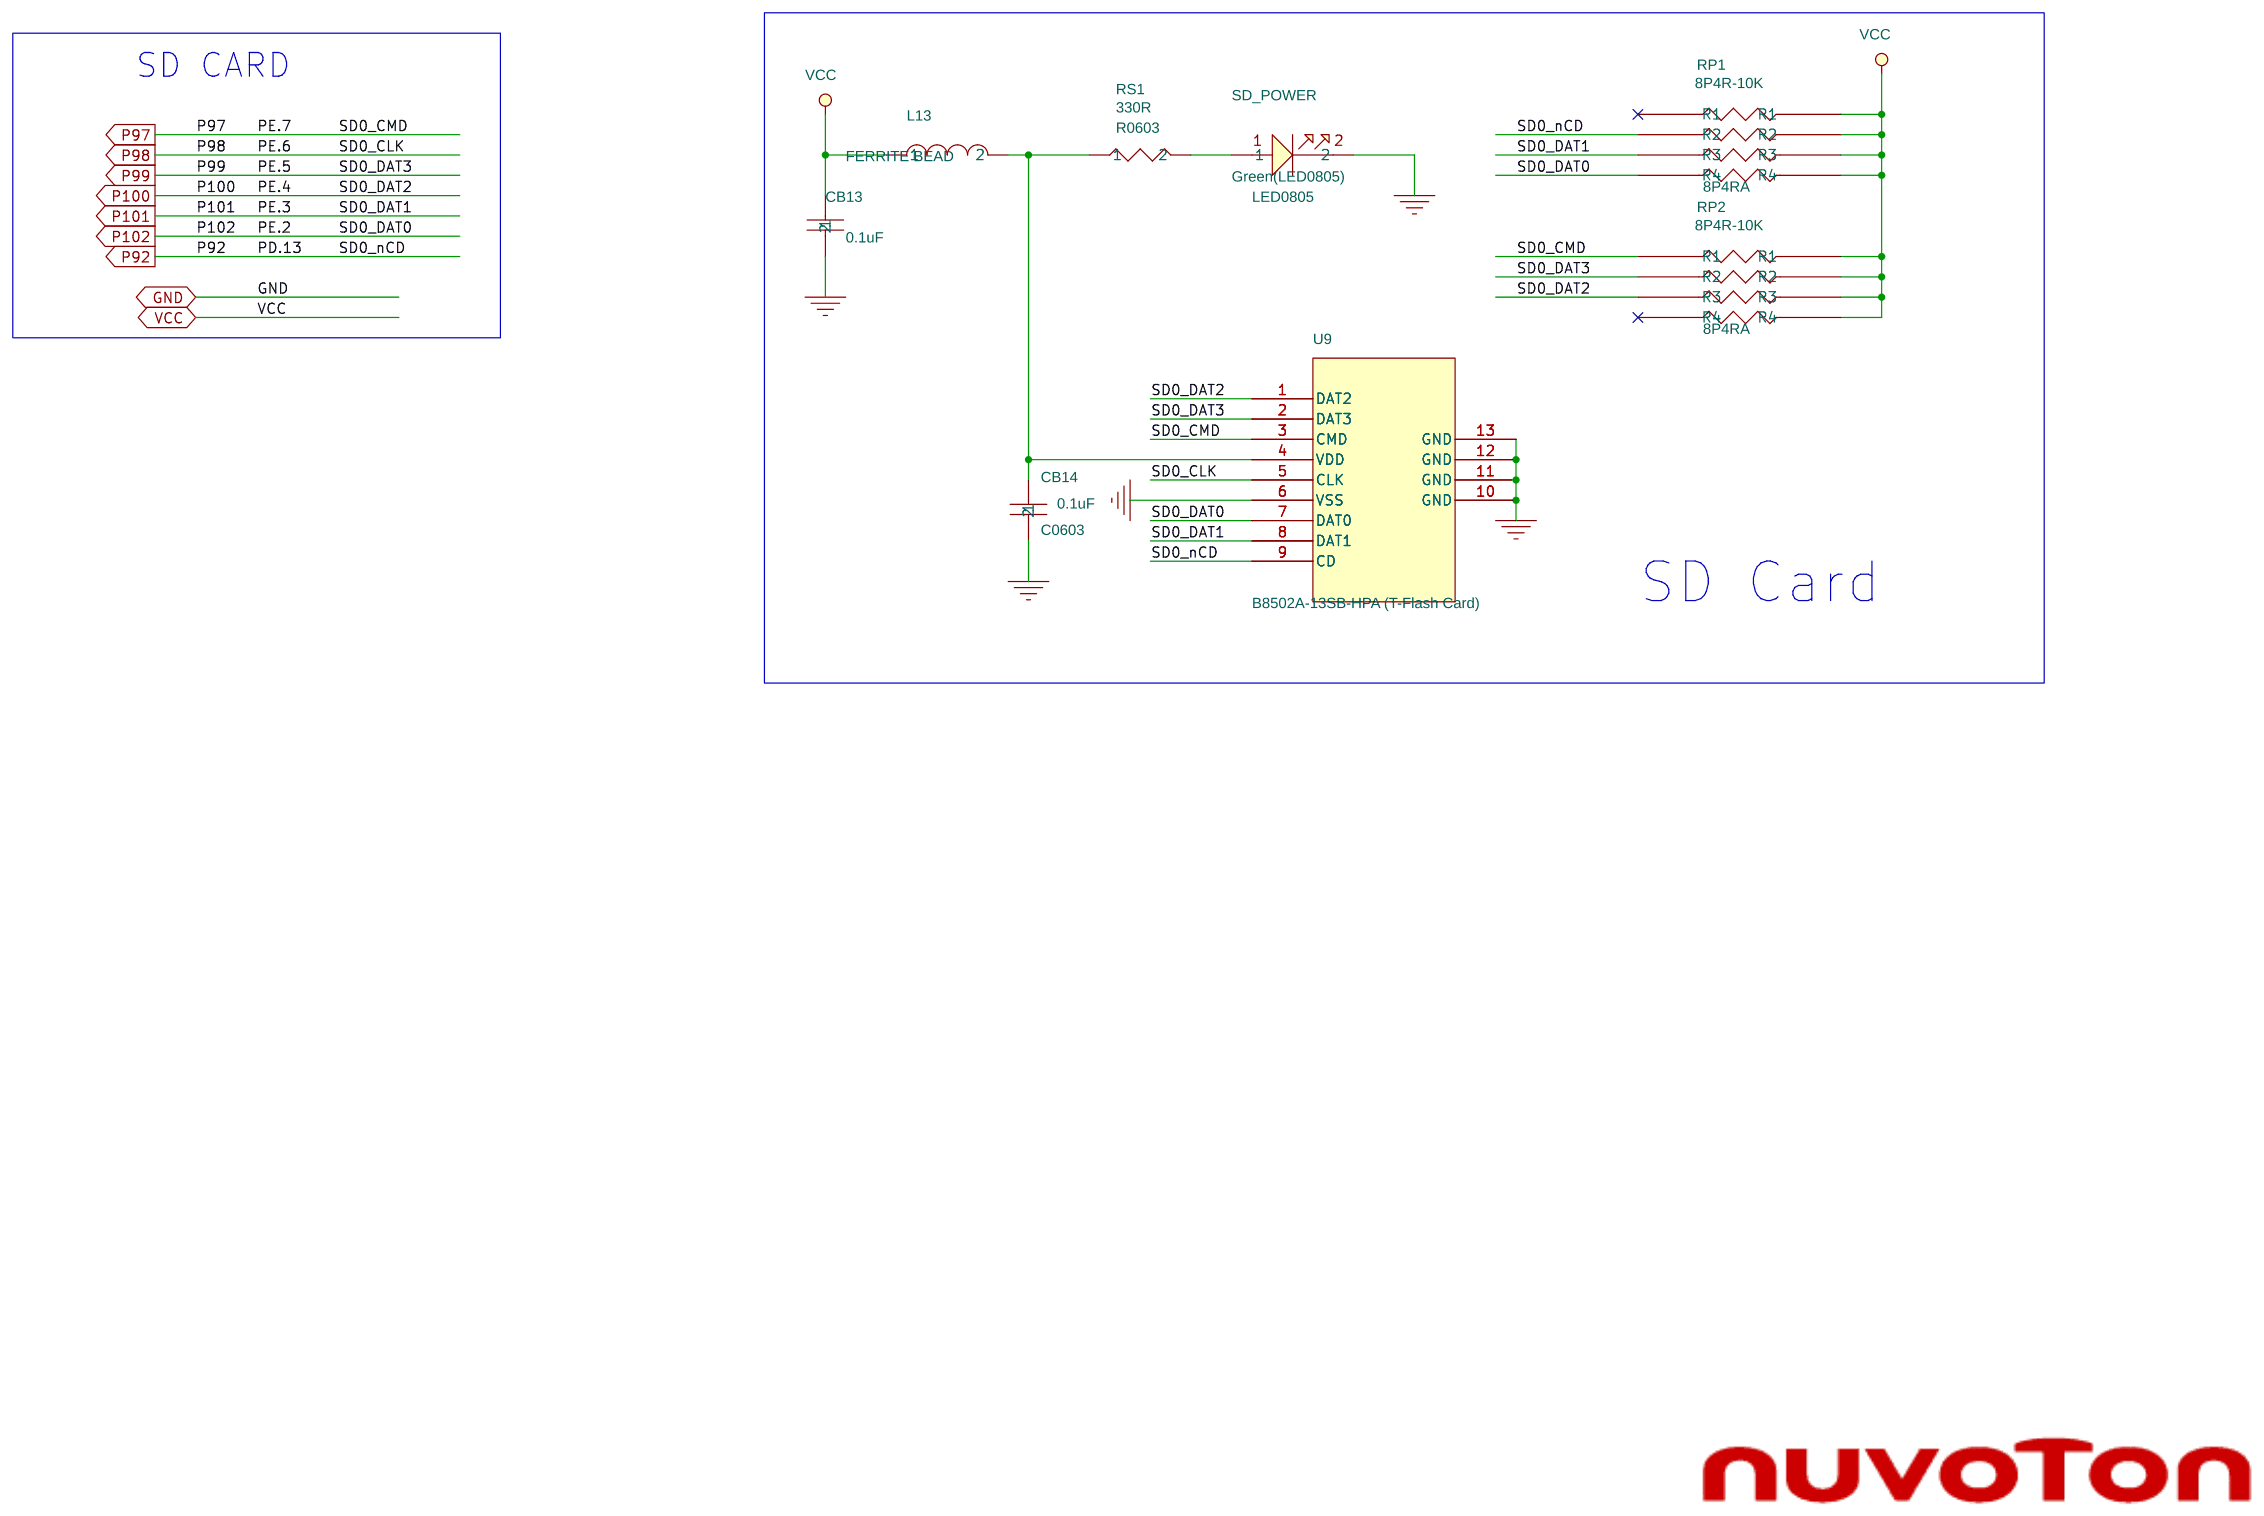
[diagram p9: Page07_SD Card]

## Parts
sheet Page00_Nu-Link-Me V3.0
BUSY  Green(LED0805)  [LED0805]
DAP  SW PUSHBUTTON  [SW-2P-SMD]
ICE  Red(LED0805)  [LED0805]
ICEC1  20pF  [C0603]
ICEC2  20pF  [C0603]
ICEC3  1uF  [C0603]
ICECB1  0.1uF  [C0603]
ICECB2  0.1uF  [C0603]
ICECT1  10uF/10V(0805)  [C0805]
ICECT2  10uF/10V(0805)  [C0805]
ICECT3  1uF  [C0603]
ICECT4  10uF  [C0603]
ICED1  SS24A  [DO-214AC]
ICEJ  USB MICRO-AB RECEP.  [MICRO_USB_AB_LS]
ICEJP1  HEADER 2,54 5X1 (NC)  [HEADER5x1]
ICEJP2  HEADER 2.54 5X2 (NC)  [HEADER5X2]
ICEL1  FERRITE BEAD  [L0603]
ICEL2  FERRITE BEAD  [L0603]
ICER1  33R  [R0603]
ICER2  33R  [R0603]
ICER3  0R  [R0603]
ICER4  10K  [R0603]
ICERP  8P4R-330  [8P4RA]
ICEU1  ACE1117C33XM+H  [SOT-223-1]
ICEU2  NUC12SRE3DE  [NCU120_LQFP_64]
ICP  Yellow(LED0805)  [LED0805]
IDLE  Red(LED0805)  [LED0805]
ISW1  2. mm DIP SWITCHES PONIES 4 SMD(HPS604-E)  [SW1X4]
RRSET  100K  [R0603]
RTCK  100K  [R0603]
RTDA1  100K  [R0603]
RTDA2  0R  [R0603]
RTDA3  33R  [R0603]
Y1  12MHz SMD X3225B  [XRGBBCNANF-27M]
sheet Page01_M2351 MCU
C1  20pF  [C0603]
C2  20pF  [C0603]
C3  20pF  [C0603]
C4  20pF  [C0603]
C5  1uF  [C0603]
CB1  0.1uF  [C0603]
CB2  0.1uF  [C0603]
CB3  470pF  [C0603]
CB15  1uF  [C0603]
CB16  0.01uF  [C0603]
CB17  1uF  [C0603]
CM1  2.2uF  [C0603]
CM2  2.2uF  [C0603]
CM3  0.1uF  [C0603]
CM4  0.1uF  [C0603]
CM5  0.1uF  [C0603]
CM6  0.1uF  [C0603]
CM7  0.1uF  [C0603]
CM8  0.1uF  [C0603]
CM10  0.1uF  [C0603]
CM11  0.1uF  [C0603]
CM12  4.7uF  [C0603]
CT1  10uF/10V(0805)  [C0805]
CT3  2.2uF(0805)  [C0805]
CT12  10uF/10V(0805)  [C0805]
ETM1  ETM Interface  [FTHS_1.27_ES_10X2]
JP1  HEADER 2.54 5X2 (NC)  [HEADER5X2]
L1  FERRITE BEAD  [L0603]
L2  FERRITE BEAD  [L0603]
L14  4.7uH  [L-VLF403215MT]
LEDG  Yellow(LED0805)  [LED0805]
LEDY  Green(LED0805)  [LED0805]
POWER  Red(LED0805)  [LED0805]
R1  NC  [R0603]
R2  10K  [R0603]
R4  330R  [R0603]
R62  10K  [R0603]
R63  10K  [R0603]
R64  330R  [R0603]
R65  330R  [R0603]
R66  51K  [R0603]
SW1  SMD«öÁä¶}Ãö6X6X5H(¶Â)¨÷¥N  [SW4-SMD]
SW2  SMD«öÁä¶}Ãö6X6X5H(¶Â)¨÷¥N  [SW4-SMD]
SW3  SMD«öÁä¶}Ãö6X6X5H(¶Â)¨÷¥N  [SW4-SMD]
T1  T POINT(NC)  [H-3.4X6]
T2  T POINT(NC)  [H-3.4X6]
T3  T POINT(NC)  [H-3.4X6]
T4  T POINT(NC)  [H-3.4X6]
U1  TC8226LQFP144  [LQFP128]
Y2  12MHz SMD X3225B  [XRGBBCNANF-27M]
Y3  X3215 32.768KHz SMD  [9HT9]
sheet Page02_USB OTG Host Device
CB6  0.1uF  [C0603]
CB7  0.1uF  [C0603]
CON2  USB MICRO-AB RECEP.  [MICRO_USB_AB_LS]
CT8  10uF/10V(0805)  [C0805]
CT9  1uF/10V  [TANT-A]
R10  33R  [R0603]
R11  33R  [R0603]
R12  10K  [R0603]
R13  4.7K  [R0603]
U3  TPS2065CDBVR-2  [SOT23-5]
sheet Page03_Power
CB8  0.1uF  [C0603]
CT10  10uF/10V  [TANT-A]
D1  SS24A  [DO-214AC]
JP2  VCC 3.3V (NC)  [HEADER2]
JP3  VCC 3.3V (NC)  [HEADER2]
JP4  GND (NC)  [HEADER2]
JP5  GND (NC)  [HEADER2]
JP10  GND (NC)  [HEADER2]
JP11  GND (NC)  [HEADER2]
L4  FERRITE BEAD  [L0603]
L5  FERRITE BEAD  [L0603]
L6  FERRITE BEAD  [L0603]
L7  FERRITE BEAD  [L0603]
L8  FERRITE BEAD  [L0603]
L9  FERRITE BEAD  [L0603]
L10  FERRITE BEAD  [L0603]
L12  FERRITE BEAD  [L0603]
U4  ACE1117C33XM+H  [SOT-223-1]
sheet Page04_MCU Connector
JP6  HEADER 2.54 16X2 (NC)  [HEADER16X2]
JP7  HEADER 2.54 16X2 (NC)  [HEADER16X2]
JP8  HEADER 2.54 16X2 (NC)  [HEADER16X2]
JP9  HEADER 2.54 16X2 (NC)  [HEADER16X2]
sheet Page05 UNO Interface Connector
NU1  HEADER 2.54 8X1 female  [SIP-8P]
NU2  HEADER 2.54 6X1 female  [SIP-6P]
NU5  HEADER 2.54 8X1 female  [SIP-8P]
NU6  HEADER 2.54 10X1 female  [SIP-10P]
NU7  header 2.54 2X4 male (NC)  [HEADER4X2]
sheet Page06_Audio Codec
C25  0.1uF  [C0603]
C27  0.1uF  [C0603]
C28  4.7uF  [C0603]
C29  4.7uF  [C0603]
C30  2.2uF  [C0603]
C32  0.1uF  [C0603]
C33  2.2uF  [C0603]
C34  2.2uF  [C0603]
C35  4.7uF  [C0603]
C36  0.1uF  [C0603]
C37  4.7uF  [C0603]
C38  1nF  [C0603]
C39  4.7uF  [C0603]
C40  1nF  [C0603]
CB12  0.1uF  [C0603]
CN2  2SJ3080-000111F   SMD  [PHONE-PJK-634M_AS]
CT11  10uF/10V  [TANT-A]
R44  1K  [R0603]
R45  0R  [R0603]
R46  0R  [R0603]
R47  4.7K  [R0603]
R48  4.7K  [R0603]
R49  1M  [R0603]
U7  ACE1117C18XM+H  [SOT-223-1]
U8  NAU88L25YGB  [QFN32_5X5]
sheet Page07_SD Card
CB13  0.1uF  [C0603]
CB14  0.1uF  [C0603]
L13  FERRITE BEAD  [L0603]
RP1  8P4R-10K  [8P4RA]
RP2  8P4R-10K  [8P4RA]
RS1  330R  [R0603]
SD_POWER  Green(LED0805)  [LED0805]
U9  B8502A-13SB-HPA (T-Flash Card)  [B8502A-13SB-HPA]
sheet Page08_WIFI Module
C41  1uF  [C0603]
C42  0.1uF  [C0603]
Q1  Si2301BDS  [SOT-23]
R67  2.2K  [R0603]
R68  10K  [R0603]
R69  10K  [R0603]
R70  10K  [R0603]
U10  ESP-03  [ESP-03]
sheet Page09_SPI Flash
CB18  0.1uF  [C0603]
CB19  0.1uF  [C0603]
R71  10K  [R0603]
U11  W77FXX  [QFN32_5x5]
U12  W77FXX   SOIC16  [SOIC16]

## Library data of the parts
BUSY LEDG SD_POWER = LED_0: Package: KP-2012; Vendor: Kingbright
DAP = SW_PUSHBUTTON_v2
ICE = LED_0_3: Package: KP-2012; Vendor: Kingbright
C1-C4 ICEC1 ICEC2 = CAP_NP
CB19 CM4 ICEC3 = CAP-C_1: Package: 0603
CB8 CB12 CB18 CM10 ICECB1 = CAP-C: Package: 0603
CM11 ICECB2 = CAP-C_2: Package: 0603
ICECT1 = CAP: Package: TANT-A
ICECT2 = CAP_1: Package: TANT-A
ICECT3 = CAP_2: Package: 0603
ICECT4 = CAP_3: Package: 0603
D1 ICED1 = DIODE_SCHOTTKY_6: Package: SOD-1231; Vendor: ROHM
ICEJ = 4X1_HEADER_5
ICEJP1 = HEADER_5
ICEJP2 JP1 = HEADER_5X2
ICEL1 L6 L14 = INDUCTOR_1
ICEL2 L2 L9 L13 = INDUCTOR
ICER1 R13 R64 R67 = R_0_3: Package: 0603
ICER2 = R_0_8: Package: 0603
ICER3 R63 = R_0_6: Package: 0603
ICER4 R2 R10 R69 R71 RS1 = R_0: Package: 0603
ICERP RP1 RP2 = R-PACK8_0
ICEU1 U4 U7 = TO-247_Regulator_10
ICEU2 = NCU120_LQFP_64
ICP POWER = LED_0_2: Package: KP-2012; Vendor: Kingbright
IDLE LEDY = LED_0_1: Package: KP-2012; Vendor: Kingbright
ISW1 = SW_DIP-4_SM
R12 R66 R68 RRSET = R_0_2: Package: 0603
R65 RTCK = R_0_4: Package: 0603
RTDA1 = R_0_7: Package: 0603
R4 R11 R70 RTDA2 = R_0_1: Package: 0603
R62 RTDA3 = R_0_5: Package: 0603
Y1 Y2 = Crystal_SMD_2
C5 = CAP-C_18: Package: 0805
CB1 = CAP-C_11: Package: 0603
CB2 = CAP-C_6: Package: 0603
CB3 = CAP-C_5: Package: 0603
CB15 = CAP-C_9: Package: 0603
CB16 = CAP-C_3: Package: 0603
CB17 = CAP-C_8: Package: 0603
CM1 = CAP-C_7: Package: 0603
CM2 = CAP-C_4: Package: 0603
CM3 = CAP-C_13: Package: 0603
CM5 = CAP-C_17: Package: 0603
CM6 = CAP-C_16: Package: 0603
CM7 = CAP-C_12: Package: 0603
CM8 = CAP-C_10: Package: 0603
CM12 = CAP-C_15: Package: 0603
CT1 CT10 CT11 = CAP: Package: TANT-R
CT3 = CAP-C_14: Package: 0603
CT12 = CAP_1: Package: TANT-R
ETM1 = ETM_Interface_0
L1 L12 = INDUCTOR_2
R1 = R
SW1 = SW_PUSHBUTTON_1: Package: DIP PUSH BOTTOM
SW2 = SW_PUSHBUTTON: Package: DIP PUSH BOTTOM
SW3 = SW_PUSHBUTTON_2: Package: DIP PUSH BOTTOM
T1-T4 = T_POINT
U1 = TC8226LQFP144_23: TC8226LQFP144: M2351_LQFP128
Y3 = MA306_SM_1
CB6 CB14 = CAP-B: Package: 0603
CB7 = CAP-B_1: Package: 0603
CON2 = USB_type_B_mini_connector
CT8 = CAP-T: Package: TANT-R
CT9 = CAP-T_1: Package: TANT-R
U3 = NCT3520U
JP2 = HEADER_2_1
JP3 = HEADER_2_4
JP4 = HEADER_2
JP5 = HEADER_2_5
JP10 = HEADER_2_2
JP11 = HEADER_2_3
L4 = INDUCTOR_4
L5 = INDUCTOR_5
L7 = INDUCTOR_3
L8 = INDUCTOR_6
L10 = INDUCTOR_7
JP6-JP9 = HEADER_16X2
NU1 = POWER_CONNECT_0
NU2 = ADC_CONNECT_0
NU5 = PWM0_CONNECT_0
NU6 = PWM1_CONNECT_1
NU7 = SPI_CONNECT_0
C25 C28 C29 C37 C39 = CAPACITOR_NON-POL: Part Number: 445-7482-1-ND; Type: Cer; Vendor: Digikey; Voltage: 10V
C27 C32 C35 C36 = CAP_NP: Part Number: 490-1519-1-ND; Type: Cer; Vendor: Digikey; Voltage: 50V
C30 C33 C34 C38 C40 = CAP_NP: 2.2uF, 16V; Part Number: 445-5157-1-ND; Type: Cer; Vendor: Digikey; Voltage: 16V
CN2 = SJ-435107RS_9: Part Number: CP-435107RS-ND; Vendor: Digikey
R44 = RESISTOR: Part Number: DNP; Vendor: Digikey
R45 R46 = RESISTOR: Part Number: P200GTR-ND; Vendor: Digikey
R47 R48 = RESISTOR: Part Number: P4.7KGTR-ND; Vendor: Digikey
R49 = RESISTOR_SM: Part Number: P220KHCT-ND; Vendor: Digikey
U8 = NAU88L24_3: Part Number: NAU88L24YG; Vendor: Nuvoton
CB13 = CAP-B_1
U9 = B8502A-13SB-HPA_(T-Flash_Card)
C41 = C_1
C42 = C
Q1 = MOSFET_P
U10 = HHW-UART-M10-1_4
U11 = M058SZAN_1: M058SZAN: W77FXX   QFN32_5x5
U12 = HHW-UART-M10-1_0

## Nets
1V8: C27.1 C32.1 CB12.1 CT11.1 L6.1 R49.2 U7.2(OUT) U7.4(OUT) U8.1(VDDA) U8.6(VDDA) U8.22(VDDC)
3VCC_IN: CB8.1 CT10.1 L5.2 NU1.4(3VCC) U4.2(OUT) U4.4(OUT)
5V_IN: D1.1 L10.2 L12.2 NU1.5(5VCC)
AVDD: CB2.2 CB15.2 CB16.2 JP9.24 L1.2 U1.120(AVDD)
GND: C1.2 C2.2 C3.2 C4.2 C5.1 C25.1 C27.2 C28.1 C29.1 C30.2 C32.2 C33.2 C35.2 C36.2 C38.2 C40.2 C41.2 C42.2 CB1.1 CB6.2 CB7.2 CB8.2 CB12.2 CB13.2 CB14.2 CB18.2 CB19.2 CM1.1 CM2.1 CM3.1 CM4.1 CM5.1 CM6.1 CM7.1 CM8.1 CM10.1 CM11.1 CM12.1 CN2.6(GND) CN2.7(MS) CON2.5(GND) CON2.6(Shield) CON2.7(Shield) CON2.8(Shield) CON2.9(Shield) CT1.2 CT8.2 CT9.2 CT10.2 CT11.2 CT12.2 DAP.2 ETM1.3(GND) ETM1.5(GND) ETM1.9(GNDDetect) ETM1.15(GND) ETM1.17(GND) ETM1.19(GND) ICEC1.2 ICEC2.2 ICEC3.2 ICECB1.1 ICECB2.1 ICECT1.2 ICECT2.2 ICECT3.2 ICECT4.2 ICEJ.5(GND) ICEJ.6(SHIELD) ICEJ.7(SHIELD) ICEJ.8(SHIELD) ICEJ.9(SHIELD) ICEJP1.5 ICEJP2.9 ICEL2.2 ICEU1.1(GND) ICEU2.16(VSS) ICEU2.61(VSS1) ICEU2.63(PVSS) ISW1.3(A3) ISW1.4(A4) JP1.10 JP4.1 JP4.2 JP5.1 JP5.2 JP6.11 JP7.11 JP8.7 JP8.20 JP9.7 JP9.16 JP10.1 JP10.2 JP11.1 JP11.2 L2.1 NU1.6(VSS) NU1.7(VSS) NU7.6(GND) POWER.2 R12.2 R70.2 SD_POWER.2 SW1.1 SW2.1 SW3.1 T1.1 T2.1 T3.1 T4.1 U1.11(VSS) U1.39(VSS) U1.52(VSS) U1.75(VSS) U1.103(VSS) U1.112(VSS) U3.2(GND) U4.1(GND) U7.1(GND) U8.5(VSSA) U8.8(VSSCP) U8.16(GPIO/CSB) U8.21(VSSD) U8.29(VSSMIC) U8.33(GND) U9.6(VSS) U9.10(GND) U9.11(GND) U9.12(GND) U9.13(GND) U10.1(GND) U11.6(GND) U12.10(GND) Y1.2(GND) Y1.4(GND) Y2.2(GND) Y2.4(GND)
VCC: C35.1 C36.1 CB1.2 CB13.1 CM3.2 CM4.2 CM5.2 CM6.2 CM7.2 CM8.2 CT1.1 CT12.1 ETM1.1(VDD) JP1.2 JP2.1 JP2.2 JP3.1 JP3.2 JP6.12 JP7.12 JP8.8 JP8.21 JP9.8 JP9.18 L1.1 L4.1 L5.1 L7.1 L8.1 L13.1 NU1.2(VDD) NU7.2(VCC) Q1.2(SOURCE) R2.1 R4.1 R13.1 R47.2 R48.2 R62.1 R63.1 R64.1 R65.1 R66.2 R68.2 RP1.2(R1) RP1.4(R2) RP1.6(R3) RP1.8(R4) RP2.2(R1) RP2.4(R2) RP2.6(R3) RP2.8(R4) U1.12(VDD) U1.40(VDD) U1.53(VDD) U1.76(VDD) U1.104(VDD) U1.114(VDD) U7.3(IN) U8.3(VDDMIC) U8.20(VDDB)
VCC_ESP-03: C41.1 C42.1 Q1.3(DRAIN) R67.1 R69.1 U10.8(VCC)
VDD5V: CB6.1 CT8.1 L9.1 L10.1 U3.5(IN)
VDDIO: CB18.1 CB19.1 CM10.2 JP8.29 L6.2 R71.1 U1.61(VDDIO) U11.3(VCC) U12.2(VDD)
VIN: D1.2 NU1.8(VIN) U4.3(IN)
12M_I: ICEC1.1 ICEU2.59(XT1_In) Y1.1(XIN)
12M_O: ICEC2.1 ICEU2.58(XT1_Out) Y1.3(XOUT)
ADAVSS: CB2.1 CB3.1 CB15.1 CB16.1 CB17.1 CT3.1 JP9.26 L2.2 NU6.7(VSS) U1.122(AVSS)
DAP: DAP.1 ICEU2.1(INT0/PB14)
FLASH_CLK: JP8.26 U1.58(PA.2) U11.7(CLK) U12.16(CLK)
FLASH_IO2: JP8.24 U1.56(PA.4) U11.4(IO2) U12.9(IO2)
FLASH_IO3: JP8.23 U1.55(PA.5) U11.5(IO3) U12.1(IO3)
FLASH_MISO: JP8.27 U1.59(UART0_TXD/PA.1) U11.2(DO) U12.8(IO1)
FLASH_MOSI: JP8.28 U1.60(UART0_RXD/PA.0) U11.8(DI) U12.15(IO0)
FLASH_SS: JP8.25 R71.2 U1.57(PA.3) U11.32(/CS) U12.7(CS/)
GPIO0_ESP03: JP7.21 U1.85(PD.6) U10.14(GPIO0)
GPIO2_ESP03: JP7.22 R69.2 U1.86(PD.5) U10.13(GPIO2)
GPIO13(UCTS)_ESP03: JP7.24 U1.88(UART0_TXD/PD.3) U10.11(GPIO13)
GPIO15(URTS)_ESP03: JP7.25 R70.1 U1.89(UART0_RXD/PD.2) U10.12(GPIO15)
GPIO16_ESP03: JP7.23 U1.87(PD.4) U10.5(GPIO16)
GREEN: BUSY.2 ICEU2.13(CTS1/PB7)
HPL: CN2.1(LEFT) U8.12(JKTIP(HPL))
HPR: CN2.2(RIGHT) U8.13(JKR1(HPR))
ICE_ADAVSS: ICEL2.1 ICEU2.43(AVSS)
ICE_AVDD: ICEL1.1 ICEU2.52(AVDD)
ICE_CLK: ICEJP1.3 ICEU2.42(ICE_CK)
ICE_DAT: ICEJP1.2 ICEU2.41(ICE_DAT)
ICE_RST: ICECT4.1 ICEJP1.4 ICER4.1 ICEU2.60(/RESET)
ICE_USBVBUS: ICEC3.1 ICECT2.1 ICED1.1 ICEJ.1(VCC) ICEU2.17(VBUS) L9.2
ICE_VCC: ICECB1.2 ICECT1.1 ICEJP1.1 ICEJP2.1 ICEL1.2 ICER4.2 ICERP.2(R1) ICERP.4(R2) ICERP.6(R3) ICERP.8(R4) ICEU1.2(OUT) ICEU1.4(OUT) ICEU2.15(VDD) ICEU2.62(VDD1) L4.2 RRSET.2 RTCK.2 RTDA1.2
ICEDM: ICEJ.2(DM) ICER1.2
ICEDP: ICEJ.3(DP) ICER2.2
ICELED: ICE.2 ICEU2.10(RX1/PB4)
ICEUSB_D+: ICER2.1 ICEU2.20(D+)
ICEUSB_D-: ICER1.1 ICEU2.19(D-)
ICPLED: ICEU2.11(TX1/PB5) ICP.2
JKR2: C37.1 C38.1 CN2.3(G/M) U8.30(JKR2)
JKSLV: C39.1 C40.1 CN2.4(M/G) U8.28(JKSLV)
M2351_RXD: ICEJP2.10 ISW1.2(A2) JP1.9 JP9.23 U1.119(PB.12/UART0_RXD)
M2351_TXD: ICEJP2.8 ISW1.1(A1) JP1.7 JP9.22 U1.118(PB.13/UART0_TXD)
MIC1+: C39.2 U8.31(MIC1+)
MIC1-: C37.2 U8.32(MIC1-)
MSG_En: ICEU2.45(PA1/ADC1) ISW1.5(B4)
N32: ICE.1 ICERP.1(R1)
N33: ICERP.3(R2) ICP.1
N34: ICERP.5(R3) IDLE.1
N35: BUSY.1 ICERP.7(R4)
N37: ICECB2.2 ICEU2.18(VDD33)
N38: ICECT3.1 ICEU2.14(LDO)
N41: ICEU2.34(PC10/SDI10) RTDA2.2
N42: ICEU2.33(PC11/SDO10) RTDA3.2
P1: JP6.1 NU2.6(A5) U1.1(PB.5)
P2: JP6.2 NU2.5(A4) U1.2(PB.4)
P3: JP6.3 NU5.5(D4) U1.3(PB.3)
P4: JP6.4 NU5.6(D5) U1.4(PB.2)
P5: JP6.5 NU5.7(D6) U1.5(PC.12/UART0_TXD)
P6: JP6.6 NU5.8(D7) U1.6(PC.11/UART0_RXD)
P7: JP6.7 NU6.2(D9) U1.7(PC.10)
P8: JP6.8 NU6.1(D8) U1.8(PC.9)
P9: JP6.9 R63.2 SW3.2 U1.9(PB.1)
P10: JP6.10 R62.2 SW2.2 U1.10(PB.0)
P13: JP6.13 LEDY.2 U1.13(PA.11)
P14: JP6.14 LEDG.2 U1.14(PA.10)
P15: JP6.15 NU5.2(D1) U1.15(PA.9)
P16: JP6.16 NU5.1(D0) U1.16(PA.8)
P17: JP6.17 U1.17(PC.13/CLKO)
P18: JP6.18 U1.18(PD.12/CLKO)
P19: JP6.19 U1.19(PD.11)
P20: JP6.20 U1.20(PD.10)
P21: JP6.21 NU6.10(I2C_SCL) U1.21(PG.2)
P22: JP6.22 NU6.9(I2C_SDA) U1.22(PG.3)
P23: JP6.23 U1.23(PG.4)
P24: JP6.24 U1.24(PF.11)
P25: JP6.25 U1.25(PF.10)
P26: JP6.26 NU6.3(D10) U1.26(PF.9)
P27: JP6.27 NU6.6(D13) U1.27(PF.8)
P28: JP6.28 NU6.5(D12) U1.28(PF.7)
P29: JP6.29 NU6.4(D11) U1.29(PF.6)
P30: CM11.2 CM12.2 JP6.30 L8.2 U1.30(VBAT)
P31: C1.1 JP6.31 U1.31(X32_IN/PF.5) Y3.2
P32: C2.1 JP6.32 U1.32(X32_OUT/PF.4) Y3.1
P33: JP8.1 U1.33(RTC_LDO/PH.4)
P34: JP8.2 U1.34(PH.5)
P35: JP8.3 U1.35(PH.6)
P36: JP8.4 U1.36(PH.7)
P37: C3.1 JP8.5 R1.1 U1.37(XT1_IN/PF.3) Y2.1(XIN)
P38: C4.1 JP8.6 R1.2 U1.38(PF.2/XT1_OUT) Y2.3(XOUT)
P41: ETM1.20(TRACEDATA[3]) JP8.9 U1.41(PE.8)
P42: ETM1.18(TRACEDATA[2]) JP8.10 U1.42(PE.9)
P43: ETM1.16(TRACEDATA[1]) JP8.11 U1.43(PE.10)
P44: ETM1.14(TRACEDATA[0]) JP8.12 U1.44(PE.11)
P45: ETM1.12(TRACECLK) JP8.13 U1.45(PE.12)
P46: JP8.14 U1.46(PE.13)
P47: JP8.15 U1.47(PC.8)
P48: JP8.16 U1.48(PC.7)
P49: JP8.17 U1.49(PC.6)
P50: JP8.18 U1.50(UART0_TXD/PA.7)
P51: JP8.19 U1.51(UART0_RXD/PA.6)
P54: CM2.2 JP8.22 U1.54(LDO_CAP)
P62: JP8.30 U1.62(PE.14)
P63: JP8.31 U1.63(PE.15)
P64: C5.2 ETM1.10(nRESET) ICER3.1 JP1.8 JP8.32 NU1.3(MCU_RESET) NU7.5(RESET) R2.2 SW1.2 U1.64(nRESET)
P65: ETM1.2(SDWIO) ICEJP2.3 JP1.4 JP7.1 R66.1 RTDA1.1 RTDA2.1 RTDA3.1 U1.65(PF.0/ICE_DAT)
P66: ETM1.4(SWDCLK) ICEJP2.5 ICEU2.35(PC9/SPCLK1) JP1.6 JP7.2 RTCK.1 U1.66(PF.1/ICE_CLK)
P67: JP7.3 R47.1 U1.67(PD.9) U8.18(SCLK)
P68: JP7.4 R48.1 U1.68(PD.8) U8.17(SDIO)
P69: CN2.5(DETECT) JP7.5 R44.1 R49.1 U1.69(PC.5)
P70: JP7.6 U1.70(PC.4) U8.26(BCLK)
P71: JP7.7 U1.71(PC.3) U8.19(MCLK)
P72: JP7.8 R46.1 U1.72(PC.2)
P73: JP7.9 R45.1 U1.73(PC.1)
P74: JP7.10 U1.74(PC.0) U8.23(FS)
P77: JP7.13 U1.77(PG.9)
P78: JP7.14 U1.78(PG.10)
P79: JP7.15 U1.79(PG.11)
P80: JP7.16 U1.80(PG.12)
P81: JP7.17 U1.81(PG.13)
P82: JP7.18 U1.82(PG.14)
P83: JP7.19 U1.83(PG.15/CLKO)
P84: JP7.20 Q1.1(GATE) R68.1 U1.84(PD.7)
P90: JP7.26 U1.90(PD.1) U10.4(URXD)
P91: JP7.27 U1.91(PD.0) U10.3(UTXD)
P92: JP7.28 RP1.3(R2) U1.92(PD.13) U9.9(CD)
P93: CB7.1 CON2.1(VBUS) CT9.1 JP7.29 L12.1 U1.93(USB_VBUS/PA.12) U3.1(OUT)
P94: JP7.30 R10.1 U1.94(USB_D-/PA.13)
P95: JP7.31 R11.1 U1.95(UART0_TXD/UDB_D+/PA.14)
P96: CON2.4(ID) JP7.32 U1.96(UART0_RXD/USB_OTG_ID/PA.15)
P97: JP9.1 RP2.1(R1) U1.97(PE.7) U9.3(CMD)
P98: JP9.2 U1.98(PE.6) U9.5(CLK)
P99: JP9.3 RP2.3(R2) U1.99(PE.5) U9.2(DAT3)
P100: JP9.4 RP2.5(R3) U1.100(PE.4) U9.1(DAT2)
P101: JP9.5 RP1.5(R3) U1.101(PE.3) U9.8(DAT1)
P102: JP9.6 RP1.7(R4) U1.102(PE.2) U9.7(DAT0)
P105: JP9.9 NU7.1(SPI2_MISO) U1.105(PE.1)
P106: JP9.10 NU7.4(SPI2_MOSI) U1.106(PE.0)
P107: JP9.11 NU7.3(SPI2_CLK) U1.107(PH.8)
P108: JP9.12 NU7.7(SPI2_SS) U1.108(PH.9)
P109: JP9.13 NU7.8(GPIO) U1.109(PH.10/UART0_TXD)
P110: JP9.14 U1.110(PH.11/UART0_RXD)
P111: JP9.15 U1.111(PD.14)
P113: JP9.17 L14.1 U1.113(VSW)
P115: CM1.2 JP9.19 L14.2 U1.115(LDO_CAP)
P116: JP9.20 R12.1 U1.116(PB.15) U3.4(EN/EN#)
P117: JP9.21 R13.2 U1.117(PB.14/CLKO) U3.3(OC#)
P123: JP9.27 NU2.1(A0) U1.123(PB.11)
P124: JP9.28 NU2.2(A1) U1.124(PB.10)
P125: JP9.29 NU2.3(A2) U1.125(PB.9/UART0_TXD)
P126: JP9.30 NU2.4(A3) U1.126(PB.8/UART0_RXD)
P127: JP9.31 NU5.3(D2) U1.127(PB.7)
P128: JP9.32 NU5.4(D3) U1.128(PB.6)
RED: ICEU2.12(RTS1/PB6) IDLE.2
RXD: ICEU2.21(PB0/RX0) ISW1.8(B1)
TICERST: ICEJP2.7 ICER3.2 ICEU2.36(PC8/SS10) RRSET.1
TXD: ICEU2.22(PB1/TX0) ISW1.7(B2)
VCOM_En: ICEU2.29(PE5) ISW1.6(B3)
VREF: CB3.2 CB17.2 CT3.2 JP9.25 L7.2 NU6.8(VREF) U1.121(VREF)
N16816390: CON2.3(D+) R11.2
N16816472: CON2.2(D-) R10.2
N16924601: C34.2 U8.11(CPCA)
N16924677: C34.1 U8.10(CPCB)
N16925551: C28.2 U8.2(MICBIAS)
N16983086: ICED1.2 ICEU1.3(IN)
N17122259: C33.1 U8.9(CPOUTN) U8.14(CPOUTN)
N17150802: POWER.1 R4.2
N17251993: CB14.1 L13.2 RS1.1 U9.4(VDD)
N17251997: RS1.2 SD_POWER.1
N17320854: C29.2 U8.4(VREF)
N17322338: LEDG.1 R64.2
N17323123: LEDY.1 R65.2
N17327670: C30.1 U8.7(CPOUTP)
N17333884: R45.2 U8.25(DACIN)
N17440747: C25.2 R44.2 U8.27(GPIO2/JKDET)
N18101603: R46.2 U8.24(ADCOUT)
N20153783: R67.2 U10.6(CH_PD)

Not connected (* = marked no-connect by the designer): ETM1 6(NC)* 7(NC)* 8(NC)* 11(NC)* 13(NC)*; ICEJ 4(NC)*; ICEJP2 2* 4* 6*; ICEU2 2(CPO1/PB13)* 3(CPO0/PB12)* 4(X32I)* 5(X32O)* 6(I2C1SCL/PA11)* 7(I2C1SDA/PA10)* 8(I2C0SCL/PA9)* 9(I2C0SDA/PA8)* 23(PB2/RTS0)* 24(PB3/CTS0)* 25(PC3/SDO00)* 26(PC2/SDI00)* 27(PC1/SPCLK0)* 28(PC0/SS00)* 30(PB11/TM3)* 31(PB10/SS01/TM2)* 32(PB9/SS11/TM1)* 37(PA15/PWM3)* 38(PA14/PWM2)* 39(PA13/PWM1)* 40(PA12/PWM0)* 44(PA0/ADC0)* 46(PA2/ADC2)* 47(PA3/ADC3)* 48(PA4/ADC4)* 49(ADC/PA5)* 50(ADC6/PA6)* 51(ADC7/PA7)* 53(CPN0/PC7)* 54(CPP0/PC6)* 55(CPN1/PC15)* 56(CPP1/PC14)* 57(INT1/PB15)* 64(STADC/TM0/PB8)*; JP1 1* 3* 5*; NU1 1(NC)*; RP1 1(R1)*; RP2 7(R4)*; U8 15(IRQ); U10 2(NC)* 7(WIFI_ANT)* 9(GPIO14)* 10(GPIO12)*; U11 1(NC) 9(NC) 10(NC) 11(NC) 12(NC) 13(NC) 14(NC) 15(NC) 16(NC) 17(NC) 18(NC) 19(NC) 20(NC) 21(NC) 22(NC) 23(NC) 24(NC) 25(NC) 26(NC) 27(NC) 28(NC) 29(NC) 30(NC) 31(NC); U12 3(IO7) 4(TEST1) 5(IO5) 6(TEST2) 11(TEST3) 12(IO6) 13(TEST4) 14(IO4)

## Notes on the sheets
sheet 1
- SPI Flash Off-page
sheet 2
- WIFI Off-page
sheet 3
- DEBUG
- ICE CONNECT IF
- POWER
- ICE Off Page
- CRYSTAL
- (RED)
- (YELLOW)
- (RED)
- LED
- (GREEN)
- MCU and USB
- RESET CIRCUIT
- VCOM&mbed switch
sheet 4
- RESET
- UNO Interface
- Analog In
- P1
  P32
- P65
  P96
- ~
- ~
- Digital In0
- BUTTON
- Digital In1
- P33
  P64
- P97
  P128
- ~
- ~
- Hole
- ICE Off Page
- ETM
- SPI Flash Off-page
- WIFI Off-page
- USB1.1 OTG&HOST
- POWER Off Page
- LDO_CAP
- VCC
- Audio CODEC
- CRYSTAL
- VREF & AVDD CAP
- ICE(Gary)
- SD CARD
- MCU bypass CAP
- LED
sheet 5
- USB1.1 OTG&HOST
- USB1.1 OTG HOST/DEVICE
- USB Host/Device
- NCT3520U Low Active
- NCT3520U
  pin3(OC#)  is
  Open Drain Pin
sheet 6
- POWER Off Page
- Power (3.3V)
   Connector
- Power
  Selector
sheet 7
- P1
  P32
- P65
  P96
- ~
- ~
- MCU CONNECTOR
- P33
  P64
- P97
  P128
- ~
- ~
sheet 8
- UNO Interface
- Analog In
- Digital In0
- Digital In1
- UNO INTERFACE
  CONNECTOR
sheet 9
- Audio CODEC
- 1.8V
- VDDA
- MICBIAS
- 1.8V
- VDDC
- I2C address x1A
- 4
- 2
- 6
- 5
- 3
- MS
- 1
- MIC-
- JKR2
- MIC+
- JKSLV
- HEADSET
sheet 10
- SD CARD
- SD Card
